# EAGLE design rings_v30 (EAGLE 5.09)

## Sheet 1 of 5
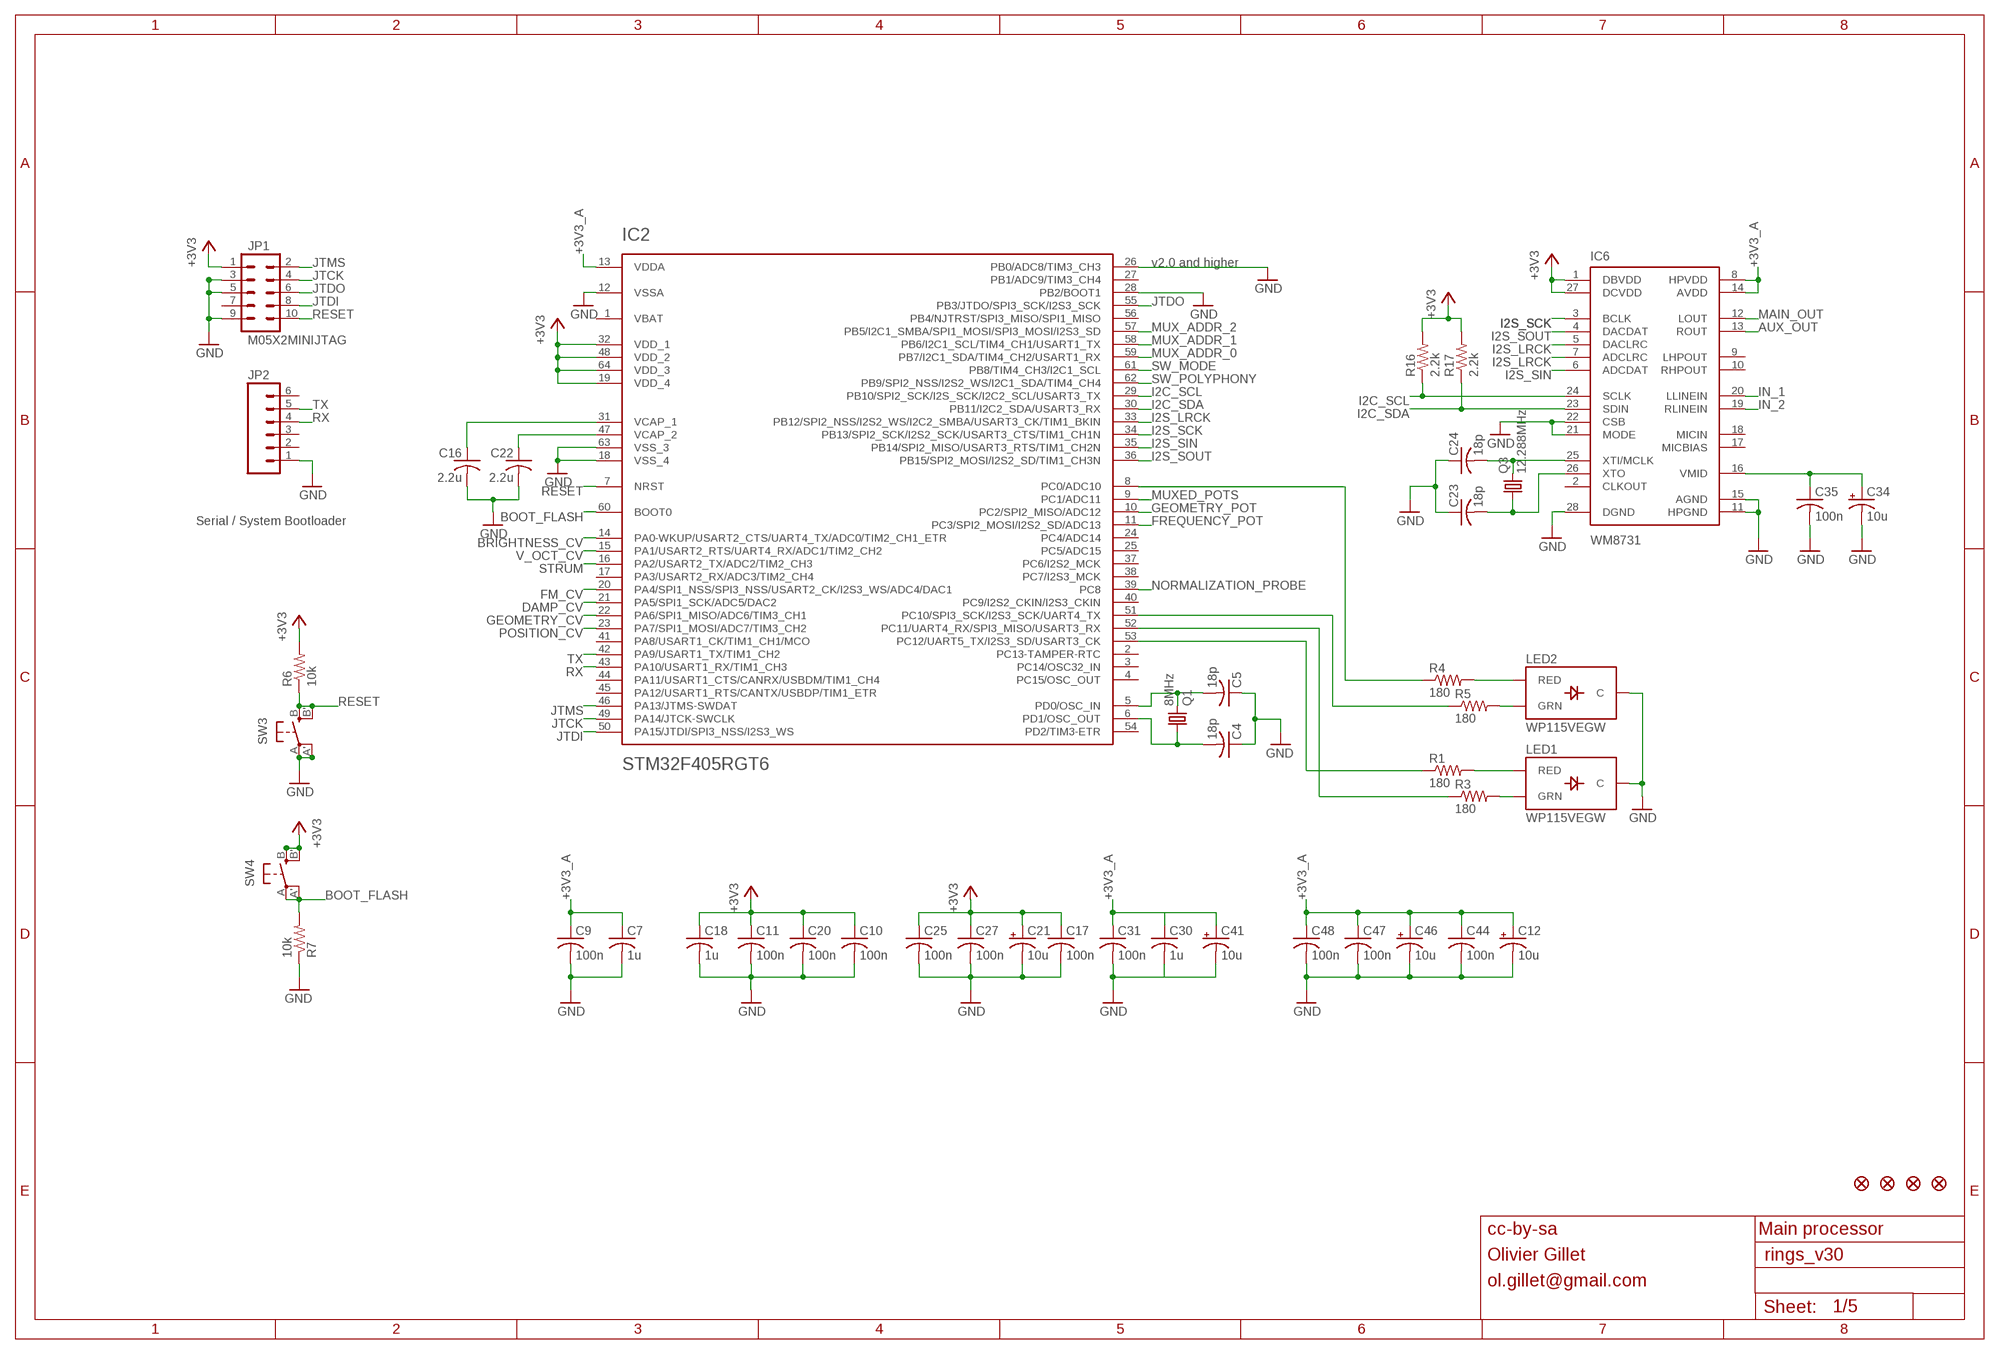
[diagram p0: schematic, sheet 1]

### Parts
C4  18p  C-USC0603  [C0603]
C5  18p  C-USC0603  [C0603]
C7  1u  C-USC0603  [C0603]
C9  100n  C-USC0603  [C0603]
C10  100n  C-USC0603  [C0603]
C11  100n  C-USC0603  [C0603]
C12  10u  CPOL-USA  [PANASONIC_A]
C16  2.2u  C-USC0805  [C0805]
C17  100n  C-USC0603  [C0603]
C18  1u  C-USC0603  [C0603]
C20  100n  C-USC0603  [C0603]
C21  10u  CPOL-USA  [PANASONIC_A]
C22  2.2u  C-USC0805  [C0805]
C23  18p  C-USC0603  [C0603]
C24  18p  C-USC0603  [C0603]
C25  100n  C-USC0603  [C0603]
C27  100n  C-USC0603  [C0603]
C30  1u  C-USC0603  [C0603]
C31  100n  C-USC0603  [C0603]
C34  10u  CPOL-USA  [PANASONIC_A]
C35  100n  C-USC0603  [C0603]
C41  10u  CPOL-USA  [PANASONIC_A]
C44  100n  C-USC0603  [C0603]
C46  10u  CPOL-USA  [PANASONIC_A]
C47  100n  C-USC0603  [C0603]
C48  100n  C-USC0603  [C0603]
F1  FIDUCIAL1X2  [FIDUCIAL-1X2]
F2  FIDUCIAL1X2  [FIDUCIAL-1X2]
F3  FIDUCIAL1X2  [FIDUCIAL-1X2]
F4  FIDUCIAL1X2  [FIDUCIAL-1X2]
IC2  STM32F405RGT6  STM32F20X  [TQFP-10X10-64]
IC6  WM8731  [SSOP28]
JP1  M05X2MINIJTAG  [2X5-1.27]
JP2  M06SIP  [1X06]
LED1  WP115VEGW  LED-BICOLOR-THROUGHHOLE  [LED-BICOLOR-THROUGHHOLE]
LED2  WP115VEGW  LED-BICOLOR-THROUGHHOLE  [LED-BICOLOR-THROUGHHOLE]
Q1  8MHz  CRYSTALHC49UP  [HC49UP]
Q3  12.288MHz  CRYSTALHC49UP  [HC49UP]
R1  180  R-US_R0603  [R0603]
R3  180  R-US_R0603  [R0603]
R4  180  R-US_R0603  [R0603]
R5  180  R-US_R0603  [R0603]
R6  10k  R-US_R0603  [R0603]
R7  10k  R-US_R0603  [R0603]
R16  2.2k  R-US_R0603  [R0603]
R17  2.2k  R-US_R0603  [R0603]
SW3  EVQQ2  [EVQ-Q2]
SW4  EVQQ2  [EVQ-Q2]

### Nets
+3V3: C10.1 C11.1 C17.1 C18.1 C20.1 C21.+ C25.1 C27.1 IC2.19(VDD_4) IC2.32(VDD_1) IC2.48(VDD_2) IC2.64(VDD_3) IC6.1(DBVDD) IC6.27(DCVDD) JP1.1 R6.2 R16.2 R17.2 SW4.B'(S1) SW4.B(S) ; also sheet 4,5
+3V3_A: C7.1 C9.1 C12.+ C30.1 C31.1 C41.+ C44.1 C46.+ C47.1 C48.1 IC2.13(VDDA) IC6.8(HPVDD) IC6.14(AVDD) ; also sheet 2,3,5
AUX_OUT: IC6.13(ROUT) ; also sheet 4
BOOT_FLASH: IC2.60(BOOT0) R7.2 SW4.A'(P1) SW4.A(P)
BRIGHTNESS_CV: IC2.14(PA0-WKUP/USART2_CTS/UART4_TX/ADC0/TIM2_CH1_ETR) ; also sheet 3
DAMP_CV: IC2.21(PA5/SPI1_SCK/ADC5/DAC2) ; also sheet 3
FM_CV: IC2.20(PA4/SPI1_NSS/SPI3_NSS/USART2_CK/I2S3_WS/ADC4/DAC1) ; also sheet 3
FREQUENCY_POT: IC2.11(PC3/SPI2_MOSI/I2S2_SD/ADC13) ; also sheet 2
GEOMETRY_CV: IC2.22(PA6/SPI1_MISO/ADC6/TIM3_CH1) ; also sheet 3
GEOMETRY_POT: IC2.10(PC2/SPI2_MISO/ADC12) ; also sheet 2
GND: C4.1 C5.1 C7.2 C9.2 C10.2 C11.2 C12.- C16.2 C17.2 C18.2 C20.2 C21.- C22.2 C23.1 C24.1 C25.2 C27.2 C30.2 C31.2 C34.- C35.2 C41.- C44.2 C46.- C47.2 C48.2 IC2.12(VSSA) IC2.18(VSS_4) IC2.26(PB0/ADC8/TIM3_CH3) IC2.28(PB2/BOOT1) IC2.63(VSS_3) IC6.11(HPGND) IC6.15(AGND) IC6.21(MODE) IC6.22(CSB) IC6.28(DGND) JP1.3 JP1.5 JP1.9 JP2.1 LED1.2(C) LED2.2(C) R7.1 SW3.A'(P1) SW3.A(P) ; also sheet 2,3,4,5
I2C_SCL: IC2.29(PB10/SPI2_SCK/I2S_SCK/I2C2_SCL/USART3_TX) IC6.24(SCLK) R16.1
I2C_SDA: IC2.30(PB11/I2C2_SDA/USART3_RX) IC6.23(SDIN) R17.1
I2S_LRCK: IC2.33(PB12/SPI2_NSS/I2S2_WS/I2C2_SMBA/USART3_CK/TIM1_BKIN) IC6.5(DACLRC) IC6.7(ADCLRC)
I2S_SCK: IC2.34(PB13/SPI2_SCK/I2S2_SCK/USART3_CTS/TIM1_CH1N) IC6.3(BCLK)
I2S_SIN: IC2.35(PB14/SPI2_MISO/USART3_RTS/TIM1_CH2N) IC6.6(ADCDAT)
I2S_SOUT: IC2.36(PB15/SPI2_MOSI/I2S2_SD/TIM1_CH3N) IC6.4(DACDAT)
IN_1: IC6.20(LLINEIN) ; also sheet 4
IN_2: IC6.19(RLINEIN) ; also sheet 4
JTCK: IC2.49(PA14/JTCK-SWCLK) JP1.4
JTDI: IC2.50(PA15/JTDI/SPI3_NSS/I2S3_WS) JP1.8
JTDO: IC2.55(PB3/JTDO/SPI3_SCK/I2S3_SCK) JP1.6
JTMS: IC2.46(PA13/JTMS-SWDAT) JP1.2
MAIN_OUT: IC6.12(LOUT) ; also sheet 4
MUX_ADDR_0: IC2.59(PB7/I2C1_SDA/TIM4_CH2/USART1_RX) ; also sheet 2
MUX_ADDR_1: IC2.58(PB6/I2C1_SCL/TIM4_CH1/USART1_TX) ; also sheet 2
MUX_ADDR_2: IC2.57(PB5/I2C1_SMBA/SPI1_MOSI/SPI3_MOSI/I2S3_SD) ; also sheet 2
MUXED_POTS: IC2.9(PC1/ADC11) ; also sheet 2
N$7: C5.2 IC2.5(PD0/OSC_IN) Q1.2
N$8: C4.2 IC2.6(PD1/OSC_OUT) Q1.1
N$12: LED1.3(RED) R1.2
N$13: C22.1 IC2.47(VCAP_2)
N$17: C34.+ C35.1 IC6.16(VMID)
N$19: C16.1 IC2.31(VCAP_1)
N$22: LED1.1(GRN) R3.2
N$27: LED2.3(RED) R4.2
N$35: LED2.1(GRN) R5.2
N$37: IC2.52(PC11/UART4_RX/SPI3_MISO/USART3_RX) R3.1
N$40: IC2.8(PC0/ADC10) R4.1
N$41: C24.2 IC6.25(XTI/MCLK) Q3.2
N$42: C23.2 IC6.26(XTO) Q3.1
N$43: IC2.53(PC12/UART5_TX/I2S3_SD/USART3_CK) R1.1
N$44: IC2.51(PC10/SPI3_SCK/I2S3_SCK/UART4_TX) R5.1
NORMALIZATION_PROBE: IC2.39(PC8) ; also sheet 4
POSITION_CV: IC2.23(PA7/SPI1_MOSI/ADC7/TIM3_CH2) ; also sheet 3
RESET: IC2.7(NRST) JP1.10 R6.1 SW3.B'(S1) SW3.B(S)
RX: IC2.43(PA10/USART1_RX/TIM1_CH3) JP2.4
STRUM: IC2.16(PA2/USART2_TX/ADC2/TIM2_CH3) ; also sheet 4
SW_MODE: IC2.61(PB8/TIM4_CH3/I2C1_SCL) ; also sheet 2
SW_POLYPHONY: IC2.62(PB9/SPI2_NSS/I2S2_WS/I2C1_SDA/TIM4_CH4) ; also sheet 2
TX: IC2.42(PA9/USART1_TX/TIM1_CH2) JP2.5
V_OCT_CV: IC2.15(PA1/USART2_RTS/UART4_RX/ADC1/TIM2_CH2) ; also sheet 3
Unconnected: IC2.2(PC13-TAMPER-RTC) IC2.3(PC14/OSC32_IN) IC2.4(PC15/OSC_OUT) IC2.17(PA3/USART2_RX/ADC3/TIM2_CH4) IC2.24(PC4/ADC14) IC2.25(PC5/ADC15) IC2.27(PB1/ADC9/TIM3_CH4) IC2.37(PC6/I2S2_MCK) IC2.38(PC7/I2S3_MCK) IC2.40(PC9/I2S2_CKIN/I2S3_CKIN) IC2.41(PA8/USART1_CK/TIM1_CH1/MCO) IC2.44(PA11/USART1_CTS/CANRX/USBDM/TIM1_CH4) IC2.45(PA12/USART1_RTS/CANTX/USBDP/TIM1_ETR) IC2.54(PD2/TIM3-ETR) IC2.56(PB4/NJTRST/SPI3_MISO/SPI1_MISO) IC6.2(CLKOUT) IC6.9(LHPOUT) IC6.10(RHPOUT) IC6.17(MICBIAS) IC6.18(MICIN) JP1.7 JP2.2 JP2.3 JP2.6

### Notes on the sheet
- v2.0 and higher
- Serial / System Bootloader
- cc-by-sa | Main processor
- Olivier Gillet
- ol.gillet@gmail.com

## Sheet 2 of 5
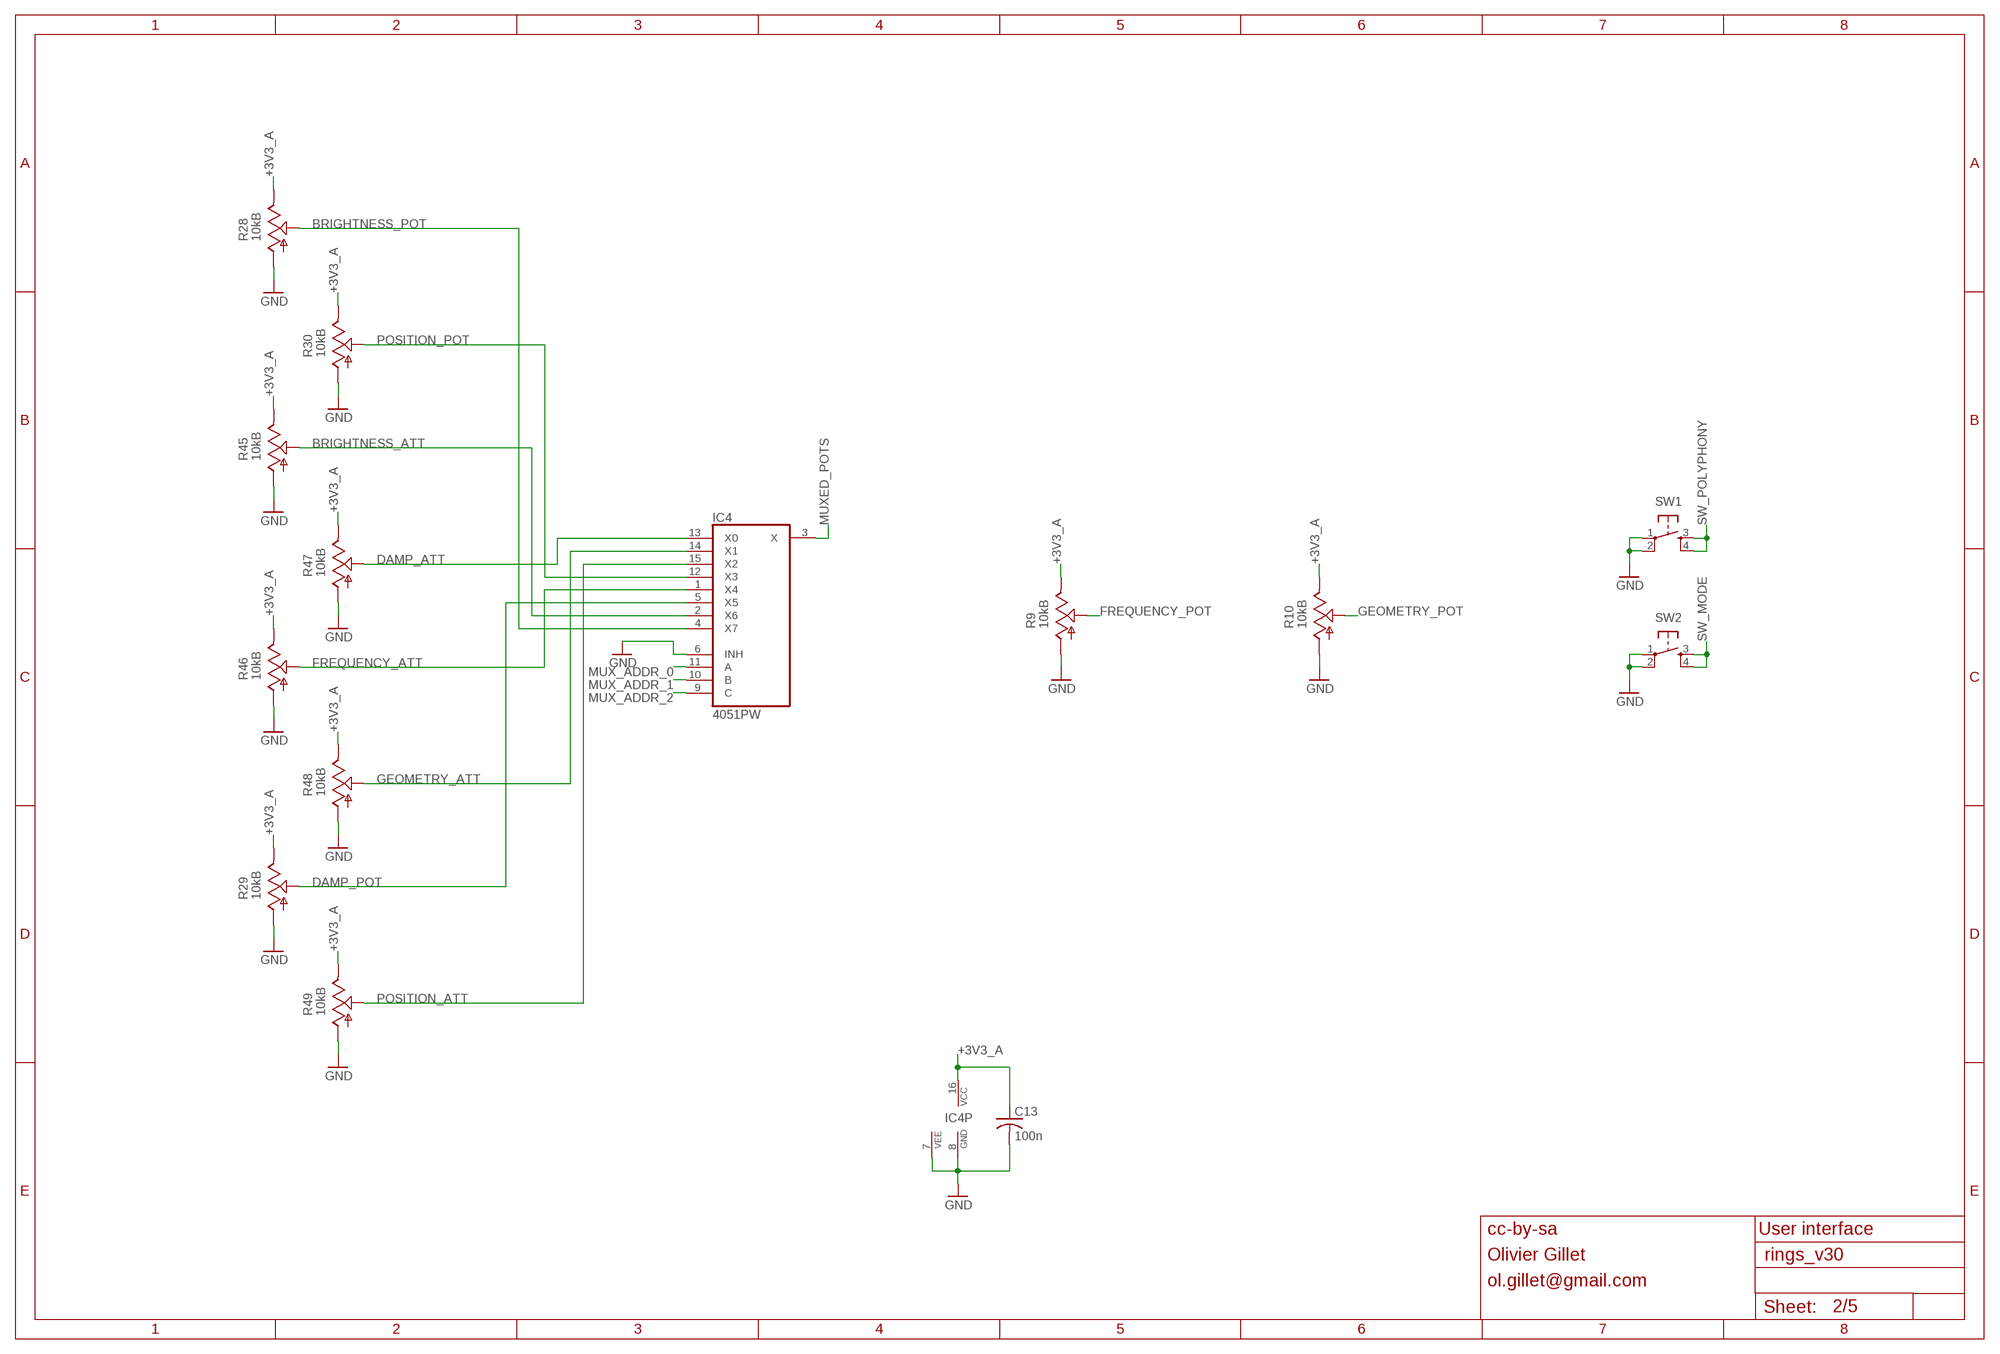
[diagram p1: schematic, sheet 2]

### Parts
C13  100n  C-USC0603  [C0603]
IC4  4051PW  [TSSOP16]
R9  10kB  POT_USVERTICAL_PS  [ALPS_POT_VERTICAL_PS]
R10  10kB  POT_USVERTICAL_PS  [ALPS_POT_VERTICAL_PS]
R28  10kB  POT_USVERTICAL_PS  [ALPS_POT_VERTICAL_PS]
R29  10kB  POT_USVERTICAL_PS  [ALPS_POT_VERTICAL_PS]
R30  10kB  POT_USVERTICAL_PS  [ALPS_POT_VERTICAL_PS]
R45  10kB  POT_USVERTICAL  [ALPS_POT_VERTICAL]
R46  10kB  POT_USVERTICAL  [ALPS_POT_VERTICAL]
R47  10kB  POT_USVERTICAL  [ALPS_POT_VERTICAL]
R48  10kB  POT_USVERTICAL  [ALPS_POT_VERTICAL]
R49  10kB  POT_USVERTICAL  [ALPS_POT_VERTICAL]
SW1  TAC_SWITCHPTH  [TACTILE-PTH]
SW2  TAC_SWITCHPTH  [TACTILE-PTH]

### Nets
+3V3_A: C13.1 IC4.16(VCC) R9.P$1(E) R10.P$1(E) R28.P$1(E) R29.P$1(E) R30.P$1(E) R45.P$1(E) R46.P$1(E) R47.P$1(E) R48.P$1(E) R49.P$1(E) ; also sheet 1,3,5
BRIGHTNESS_ATT: IC4.2(X6) R45.P$2(S)
BRIGHTNESS_POT: IC4.4(X7) R28.P$2(S)
DAMP_ATT: IC4.13(X0) R47.P$2(S)
DAMP_POT: IC4.5(X5) R29.P$2(S)
FREQUENCY_ATT: IC4.1(X4) R46.P$2(S)
FREQUENCY_POT: R9.P$2(S) ; also sheet 1
GEOMETRY_ATT: IC4.14(X1) R48.P$2(S)
GEOMETRY_POT: R10.P$2(S) ; also sheet 1
GND: C13.2 IC4.6(INH) IC4.7(VEE) IC4.8(GND) R9.P$3(A) R10.P$3(A) R28.P$3(A) R29.P$3(A) R30.P$3(A) R45.P$3(A) R46.P$3(A) R47.P$3(A) R48.P$3(A) R49.P$3(A) SW1.1 SW1.2 SW2.1 SW2.2 ; also sheet 1,3,4,5
MUX_ADDR_0: IC4.11(A) ; also sheet 1
MUX_ADDR_1: IC4.10(B) ; also sheet 1
MUX_ADDR_2: IC4.9(C) ; also sheet 1
MUXED_POTS: IC4.3(X) ; also sheet 1
POSITION_ATT: IC4.15(X2) R49.P$2(S)
POSITION_POT: IC4.12(X3) R30.P$2(S)
SW_MODE: SW2.3 SW2.4 ; also sheet 1
SW_POLYPHONY: SW1.3 SW1.4 ; also sheet 1

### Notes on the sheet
- cc-by-sa | User interface
- Olivier Gillet
- ol.gillet@gmail.com

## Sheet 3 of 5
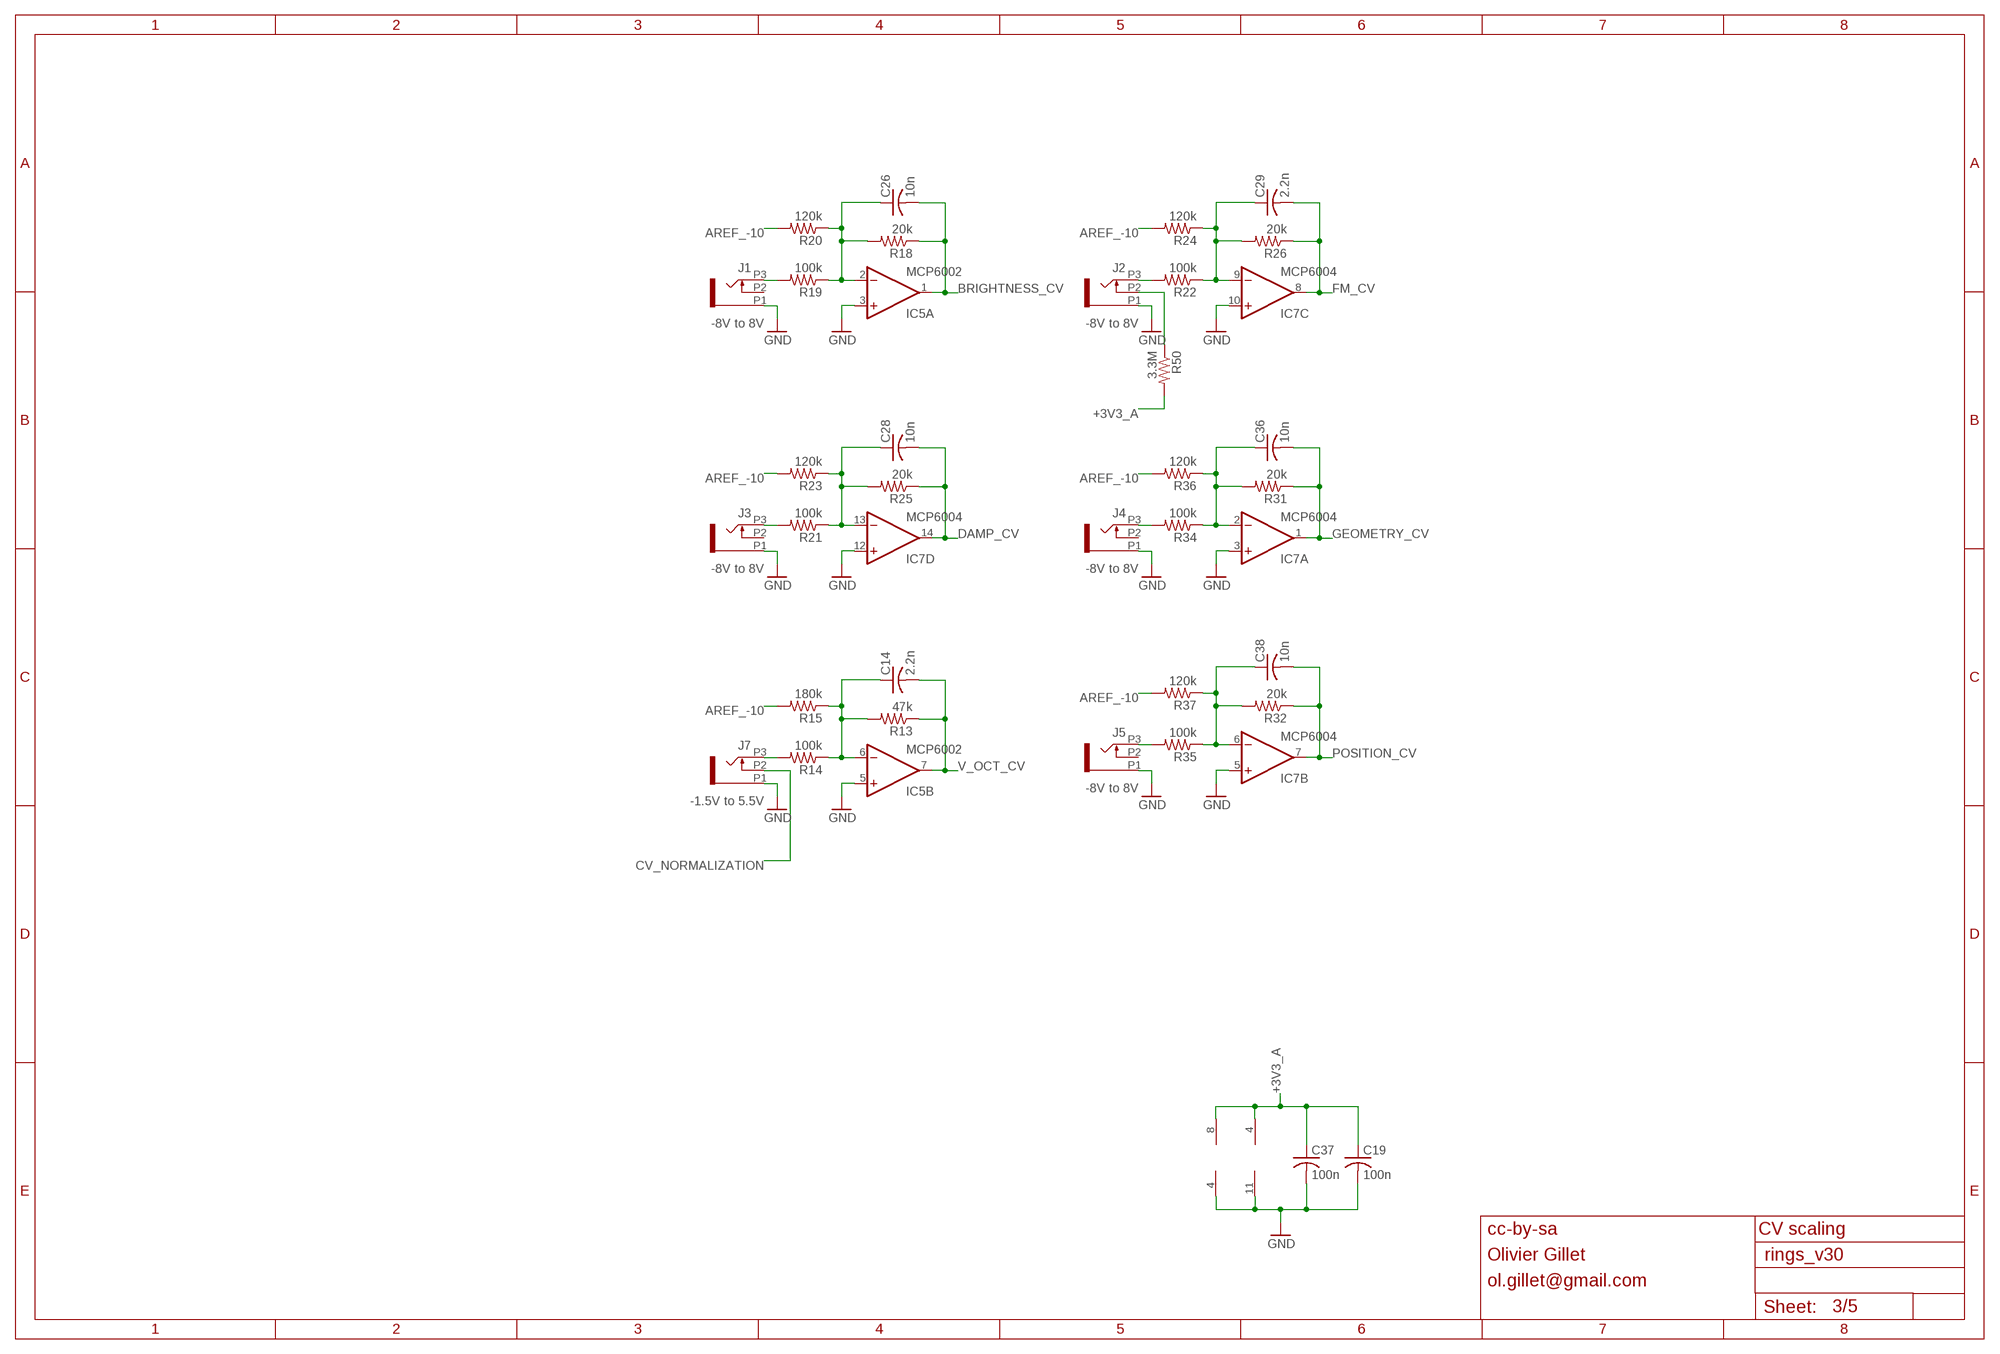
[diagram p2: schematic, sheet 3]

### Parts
C14  2.2n  C-USC0603  [C0603]
C19  100n  C-USC0603  [C0603]
C26  10n  C-USC0603  [C0603]
C28  10n  C-USC0603  [C0603]
C29  2.2n  C-USC0603  [C0603]
C36  10n  C-USC0603  [C0603]
C37  100n  C-USC0603  [C0603]
C38  10n  C-USC0603  [C0603]
IC5  MCP6002  TL072D  [SO08]
IC7  MCP6004  TL074D  [SO14]
J1  PJ301_THONKICONN6  [WQP_PJ_301M6]
J2  PJ301_THONKICONN6  [WQP_PJ_301M6]
J3  PJ301_THONKICONN6  [WQP_PJ_301M6]
J4  PJ301_THONKICONN6  [WQP_PJ_301M6]
J5  PJ301_THONKICONN6  [WQP_PJ_301M6]
J7  PJ301_THONKICONN6  [WQP_PJ_301M6]
R13  47k  R-US_R0603  [R0603]
R14  100k  R-US_R0603  [R0603]
R15  180k  R-US_R0603  [R0603]
R18  20k  R-US_R0603  [R0603]
R19  100k  R-US_R0603  [R0603]
R20  120k  R-US_R0603  [R0603]
R21  100k  R-US_R0603  [R0603]
R22  100k  R-US_R0603  [R0603]
R23  120k  R-US_R0603  [R0603]
R24  120k  R-US_R0603  [R0603]
R25  20k  R-US_R0603  [R0603]
R26  20k  R-US_R0603  [R0603]
R31  20k  R-US_R0603  [R0603]
R32  20k  R-US_R0603  [R0603]
R34  100k  R-US_R0603  [R0603]
R35  100k  R-US_R0603  [R0603]
R36  120k  R-US_R0603  [R0603]
R37  120k  R-US_R0603  [R0603]
R50  3.3M  R-US_R0603  [R0603]

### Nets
+3V3_A: C19.1 C37.1 IC5.8(P:V+) IC7.4(P:V+) R50.2 ; also sheet 1,2,5
AREF_-10: R15.2 R20.2 R23.2 R24.2 R36.2 R37.2 ; also sheet 5
BRIGHTNESS_CV: C26.2 IC5.1(A:OUT) R18.1 ; also sheet 1
CV_NORMALIZATION: J7.P2 ; also sheet 4
DAMP_CV: C28.2 IC7.14(D:OUT) R25.1 ; also sheet 1
FM_CV: C29.2 IC7.8(C:OUT) R26.1 ; also sheet 1
GEOMETRY_CV: C36.2 IC7.1(A:OUT) R31.1 ; also sheet 1
GND: C19.2 C37.2 IC5.3(A:+IN) IC5.4(P:V-) IC5.5(B:+IN) IC7.3(A:+IN) IC7.5(B:+IN) IC7.10(C:+IN) IC7.11(P:V-) IC7.12(D:+IN) J1.P1 J2.P1 J3.P1 J4.P1 J5.P1 J7.P1 ; also sheet 1,2,4,5
N$1: J1.P3 R19.2
N$2: C26.1 IC5.2(A:-IN) R18.2 R19.1 R20.1
N$3: J7.P3 R14.2
N$4: J2.P3 R22.2
N$5: C29.1 IC7.9(C:-IN) R22.1 R24.1 R26.2
N$6: J4.P3 R34.2
N$10: J3.P3 R21.2
N$11: C28.1 IC7.13(D:-IN) R21.1 R23.1 R25.2
N$14: C14.1 IC5.6(B:-IN) R13.2 R14.1 R15.1
N$15: C36.1 IC7.2(A:-IN) R31.2 R34.1 R36.1
N$26: J5.P3 R35.2
N$30: C38.1 IC7.6(B:-IN) R32.2 R35.1 R37.1
N$38: J2.P2 R50.1
POSITION_CV: C38.2 IC7.7(B:OUT) R32.1 ; also sheet 1
V_OCT_CV: C14.2 IC5.7(B:OUT) R13.1 ; also sheet 1
Unconnected: J1.P2 J3.P2 J4.P2 J5.P2

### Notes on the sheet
- -8V to 8V | -8V to 8V
- -8V to 8V | -8V to 8V
- -8V to 8V
- -1.5V to 5.5V
- cc-by-sa | CV scaling
- Olivier Gillet
- ol.gillet@gmail.com

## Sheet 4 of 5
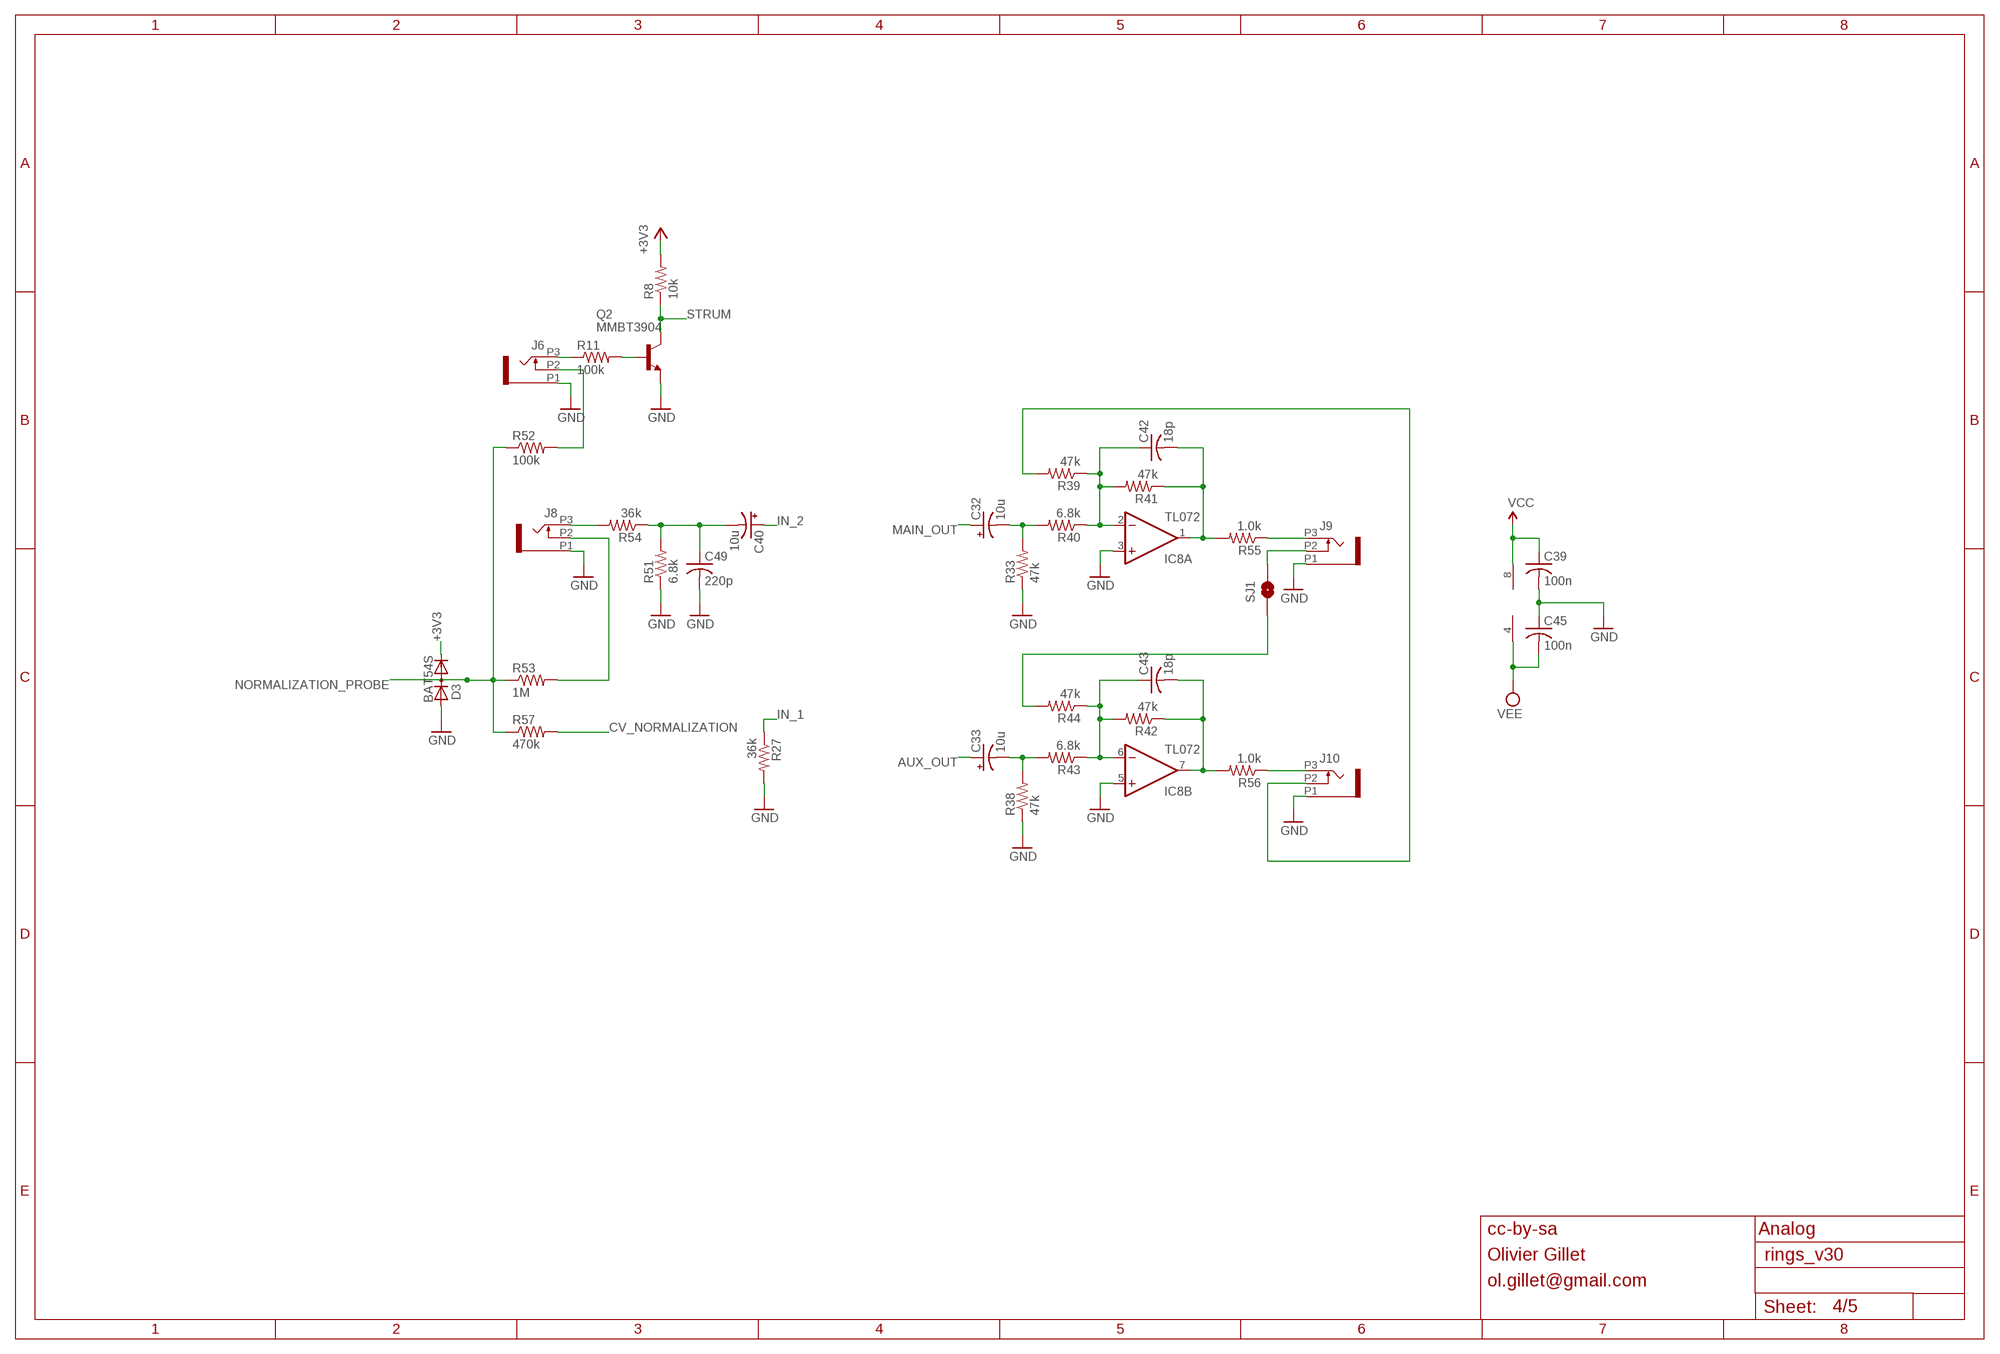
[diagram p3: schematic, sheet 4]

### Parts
C32  10u  CPOL-USA  [PANASONIC_A]
C33  10u  CPOL-USA  [PANASONIC_A]
C39  100n  C-USC0603  [C0603]
C40  10u  CPOL-USA  [PANASONIC_A]
C42  18p  C-USC0603  [C0603]
C43  18p  C-USC0603  [C0603]
C45  100n  C-USC0603  [C0603]
C49  220p  C-USC0603  [C0603]
D3  BAT54S  DIODE_2CACA-SOT23  [SOT23]
IC8  TL072  TL072D  [SO08]
J6  PJ301_THONKICONN6  [WQP_PJ_301M6]
J8  PJ301_THONKICONN6  [WQP_PJ_301M6]
J9  PJ301_THONKICONN6  [WQP_PJ_301M6]
J10  PJ301_THONKICONN6  [WQP_PJ_301M6]
Q2  MMBT3904  MMBT3904LT1-NPN-SOT23-BEC  [SOT23-BEC]
R8  10k  R-US_R0603  [R0603]
R11  100k  R-US_R0603  [R0603]
R27  36k  R-US_R0603  [R0603]
R33  47k  R-US_R0603  [R0603]
R38  47k  R-US_R0603  [R0603]
R39  47k  R-US_R0603  [R0603]
R40  6.8k  R-US_R0603  [R0603]
R41  47k  R-US_R0603  [R0603]
R42  47k  R-US_R0603  [R0603]
R43  6.8k  R-US_R0603  [R0603]
R44  47k  R-US_R0603  [R0603]
R51  6.8k  R-US_R0603  [R0603]
R52  100k  R-US_R0603  [R0603]
R53  1M  R-US_R0603  [R0603]
R54  36k  R-US_R0603  [R0603]
R55  1.0k  R-US_R0603  [R0603]
R56  1.0k  R-US_R0603  [R0603]
R57  470k  R-US_R0603  [R0603]
SJ1  SOLDERJUMPERNC2  [SJ_2S-NOTRACE]

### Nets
+3V3: D3.2(C) R8.2 ; also sheet 1,5
AUX_OUT: C33.+ ; also sheet 1
CV_NORMALIZATION: R57.2 ; also sheet 3
GND: C39.2 C45.1 C49.2 D3.1(A) IC8.3(A:+IN) IC8.5(B:+IN) J6.P1 J8.P1 J9.P1 J10.P1 Q2.E R27.2 R33.1 R38.1 R51.1 ; also sheet 1,2,3,5
IN_1: R27.1 ; also sheet 1
IN_2: C40.+ ; also sheet 1
MAIN_OUT: C32.+ ; also sheet 1
N$9: J6.P3 R11.1
N$18: C40.- C49.1 R51.2 R54.1
N$20: J6.P2 R52.2
N$21: J8.P3 R54.2
N$23: C33.- R38.2 R43.2
N$25: C43.1 IC8.6(B:-IN) R42.2 R43.1 R44.1
N$28: C43.2 IC8.7(B:OUT) R42.1 R56.2
N$29: J10.P3 R56.1
N$31: C32.- R33.2 R40.2
N$32: C42.1 IC8.2(A:-IN) R39.1 R40.1 R41.2
N$33: C42.2 IC8.1(A:OUT) R41.1 R55.2
N$34: J9.P3 R55.1
N$39: J8.P2 R53.2
N$45: J10.P2 R39.2
N$46: R44.2 SJ1.1
N$47: J9.P2 SJ1.2
N$66: Q2.B R11.2
NORMALIZATION_PROBE: D3.3(AC) R52.1 R53.1 R57.1 ; also sheet 1
STRUM: Q2.C R8.1 ; also sheet 1
VCC: C39.1 IC8.8(P:V+) ; also sheet 5
VEE: C45.2 IC8.4(P:V-) ; also sheet 5

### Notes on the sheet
- cc-by-sa | Analog
- Olivier Gillet
- ol.gillet@gmail.com

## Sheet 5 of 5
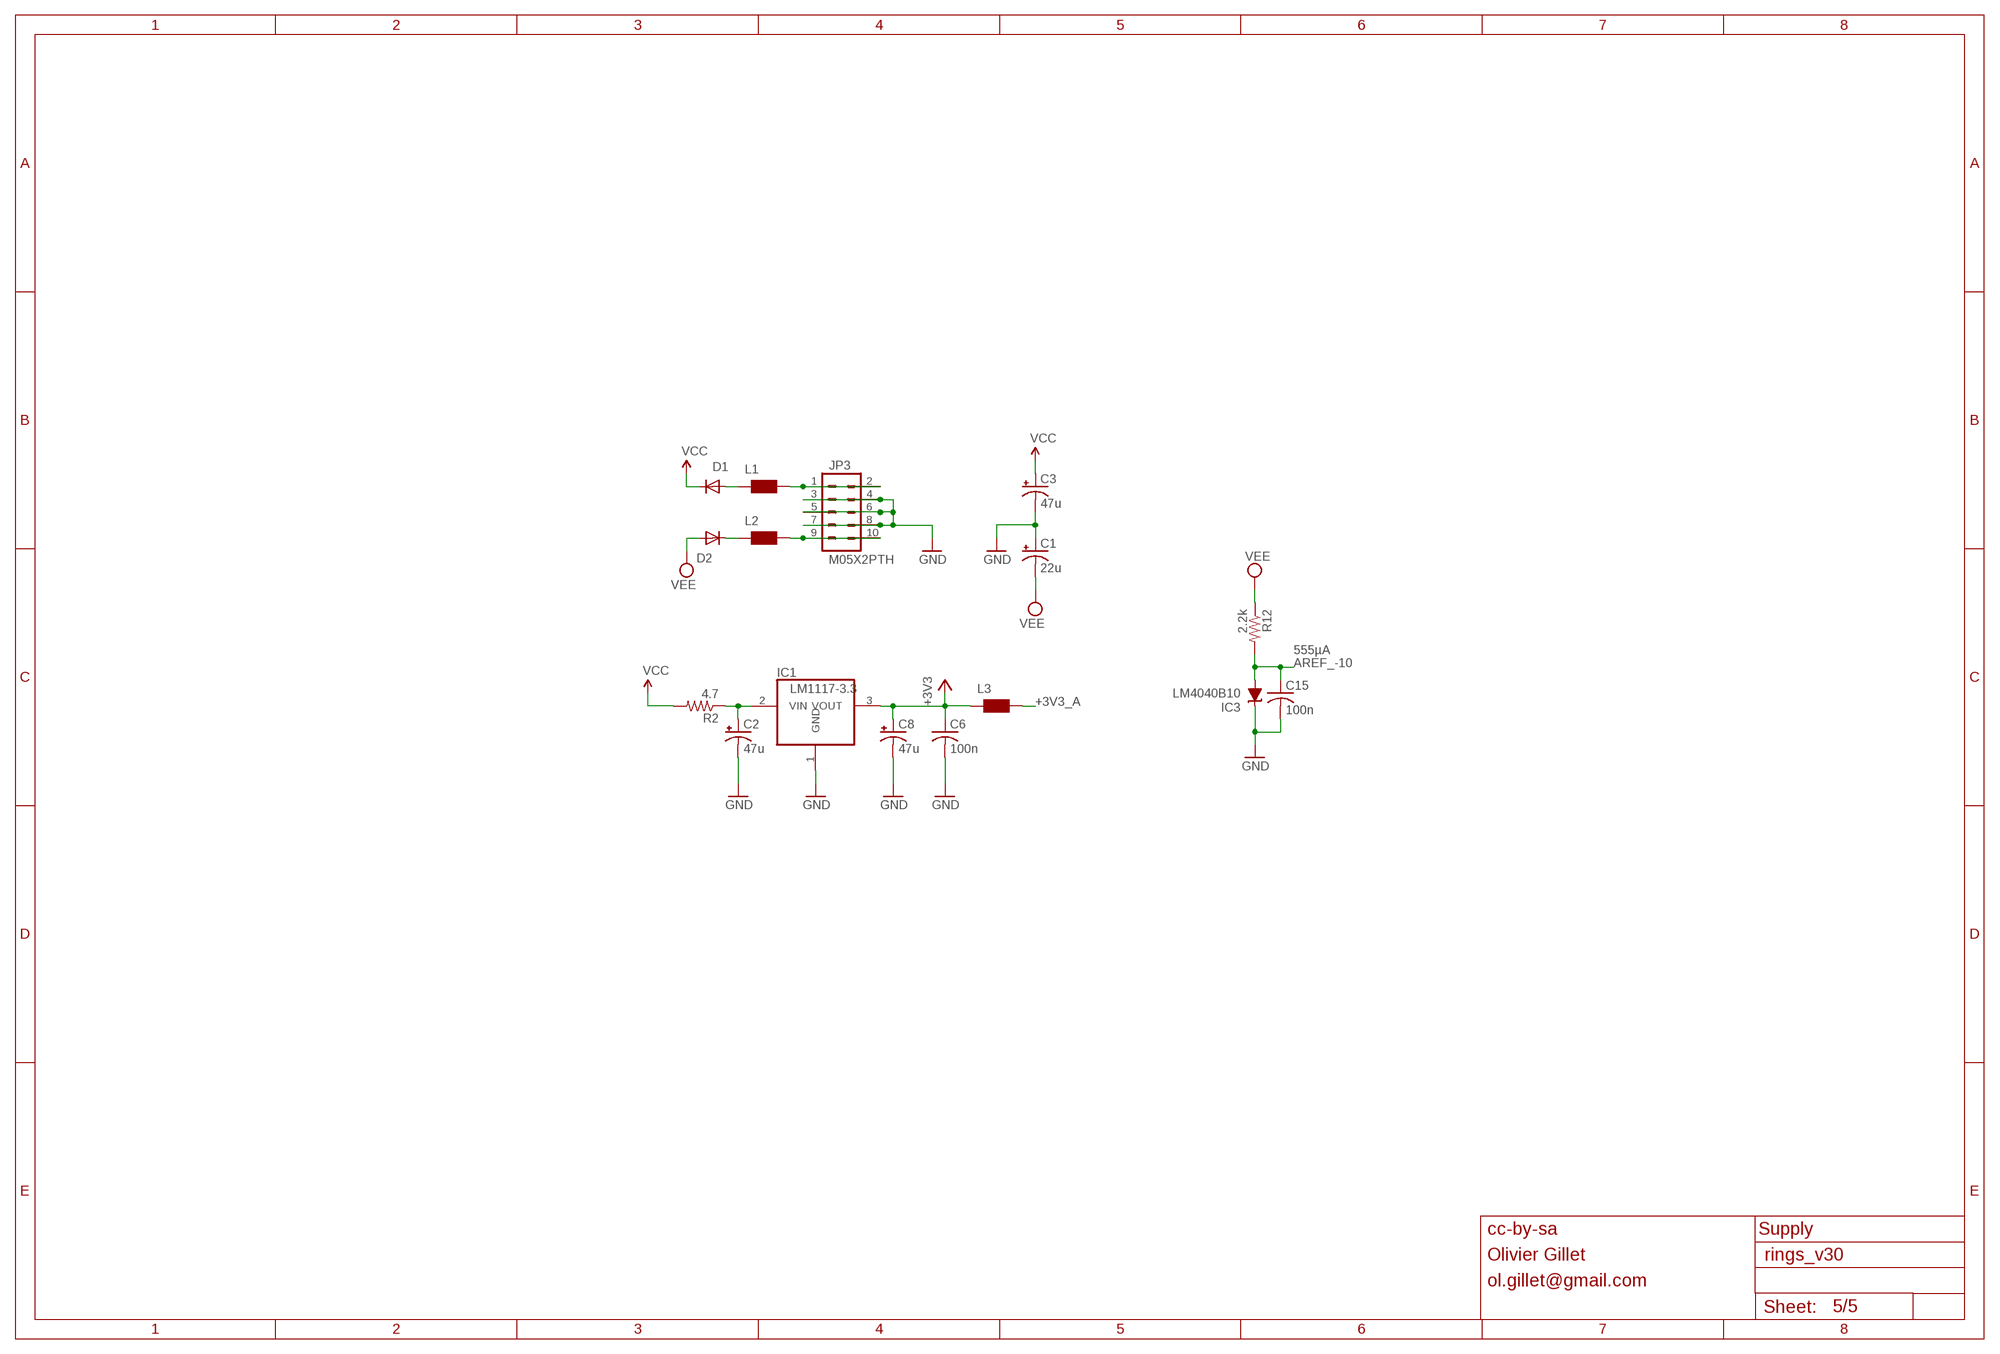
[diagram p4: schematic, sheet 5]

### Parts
C1  22u  CPOL-USC  [PANASONIC_C]
C2  47u  CPOL-USD  [PANASONIC_D]
C3  47u  CPOL-USD  [PANASONIC_D]
C6  100n  C-USC0603  [C0603]
C8  47u  CPOL-USD  [PANASONIC_D]
C15  100n  C-USC0603  [C0603]
D1  1N5819HW  DIODE-SOD123  [SOD123]
D2  1N5819HW  DIODE-SOD123  [SOD123]
IC1  LM1117-3.3  REG1117T  [TO252]
IC3  LM4040B10  LM4041B12DBZ  [DBZ_R-PDSO-G3]
JP3  M05X2PTH  [AVR_ICSP]
L1  WE-CBF_0603  [0603]
L2  WE-CBF_0603  [0603]
L3  WE-CBF_0603  [0603]
R2  4.7  R-US_R1206  [R1206]
R12  2.2k  R-US_R0603  [R0603]

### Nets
+3V3: C6.1 C8.+ IC1.3(VOUT) L3.1 ; also sheet 1,4
+3V3_A: L3.2 ; also sheet 1,2,3
AREF_-10: C15.1 IC3.2(A) R12.2 ; also sheet 3
GND: C1.+ C2.- C3.- C6.2 C8.- C15.2 IC1.1(GND) IC3.1(C) JP3.3 JP3.4 JP3.5 JP3.6 JP3.7 JP3.8 ; also sheet 1,2,3,4
N$16: C2.+ IC1.2(VIN) R2.1
N$24: D1.A L1.1
N$36: D2.C L2.1
N$56: JP3.1 JP3.2 L1.2
N$64: JP3.9 JP3.10 L2.2
VCC: C3.+ D1.C R2.2 ; also sheet 4
VEE: C1.- D2.A R12.1 ; also sheet 4

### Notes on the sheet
- 555µA
- cc-by-sa | Supply
- Olivier Gillet
- ol.gillet@gmail.com

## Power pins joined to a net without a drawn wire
VBAT: IC2.1(VBAT)

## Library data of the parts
C1-C3 C8 C12 C21 C32-C34 C40 C41 C46 = rcl:CPOL-US: POLARIZED CAPACITOR, American symbol
C4-C7 C9-C11 C13-C20 C22-C31 C35-C39 C42-C45 C47-C49 = rcl:C-US: CAPACITOR, American symbol
D1 D2 = diode:DIODE-: DIODE
D3 = diode:DIODE_2CACA-: 2 Diodes - Cathode-Anode|Cathode-Anode
F1-F4 = SparkFun:FIDUCIAL: Fiducial Alignment Points
IC1 = og-vreg:REG1117: 800mA and 1A Low Dropout (LDO) Positive Regulator 1.8V, 2.5V, 2.85V, 3.3V, 5V, and Adj
IC2 = og-stm32f2:STM32F20X
IC3 = texas:LM4041: PRECISION MICROPOWER SHUNT VOLTAGE REFERENCE
IC4 = og-ics:4051: 8-channel ANALOG MULTIPLEXER
IC5 = gm-ics:TL072: OP AMP
IC6 = og-dac:WM8731
IC7 = gm-ics:TL074: OP AMP
IC8 = og-linear:TL072: OP AMP
J1-J10 = og-pj301:PJ301_THONKICONN
JP1 JP3 = og-header:M05X2: Header 5x2 Standard 10-pin dual row 0.1" header. Commonly used with AVR-ISP. Use with Spark Fun Electronics SKU: PRT-00778
JP2 = SparkFun:M06: Header 6 Standard 6-pin 0.1" header. Use with straight break away headers (SKU : PRT-00116), right angle break away headers (PRT-00553), swiss pins (PRT-00743), machine pins (PRT-00117), and female headers (PRT-00115). Molex polarized connector foot print use with SKU : PRT-08094 with associated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
L1-L3 = wuerth-elektronik:WE-CBF: SMD EMI Suppression Ferrite Beads
LED1 LED2 = og-leds:LED-BICOLOR-THROUGHHOLE
Q1 Q3 = crystal:CRYSTAL: CRYSTAL
Q2 = transistor:*-NPN-: NPN Transistror BF959 corrected 2008.03.06
R1-R8 R11-R27 R31-R44 R50-R57 = rcl:R-US_: RESISTOR, American symbol
R9 R10 R28-R30 R45-R49 = og-pots:POT_US
SJ1 = SparkFun:SOLDERJUMPER: Solder Jumper
SW1 SW2 = SparkFun:TAC_SWITCH: Momentary Switch Button commonly used for reset or general input. Spark Fun Electronics SKU : COM-00097
SW3 SW4 = adafruit:EVQQ2: SMT 6mm switch, EVQQ2 series http://www.ladyada.net/library/eagle

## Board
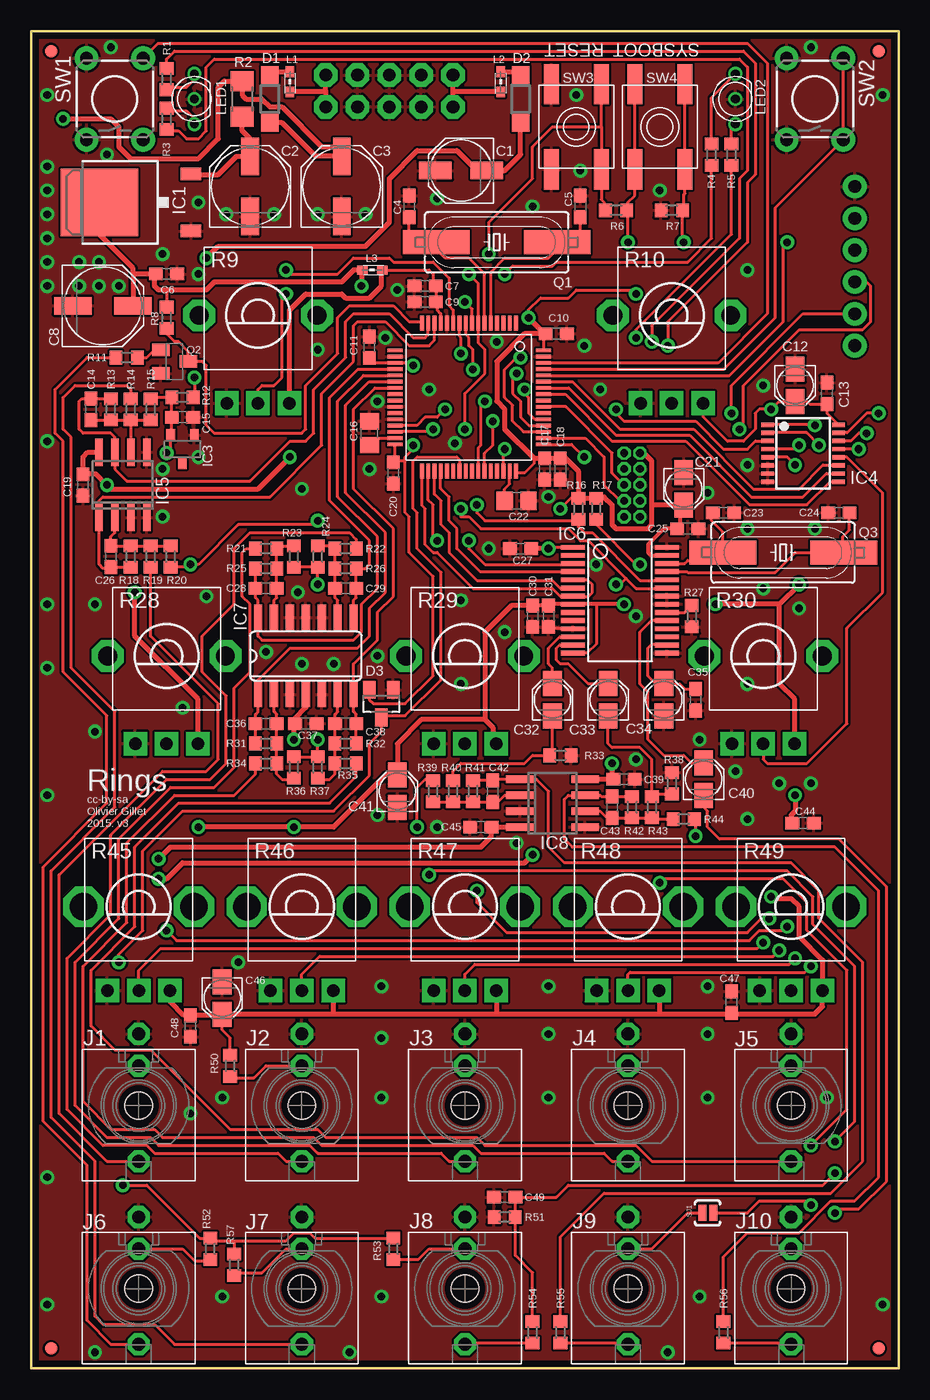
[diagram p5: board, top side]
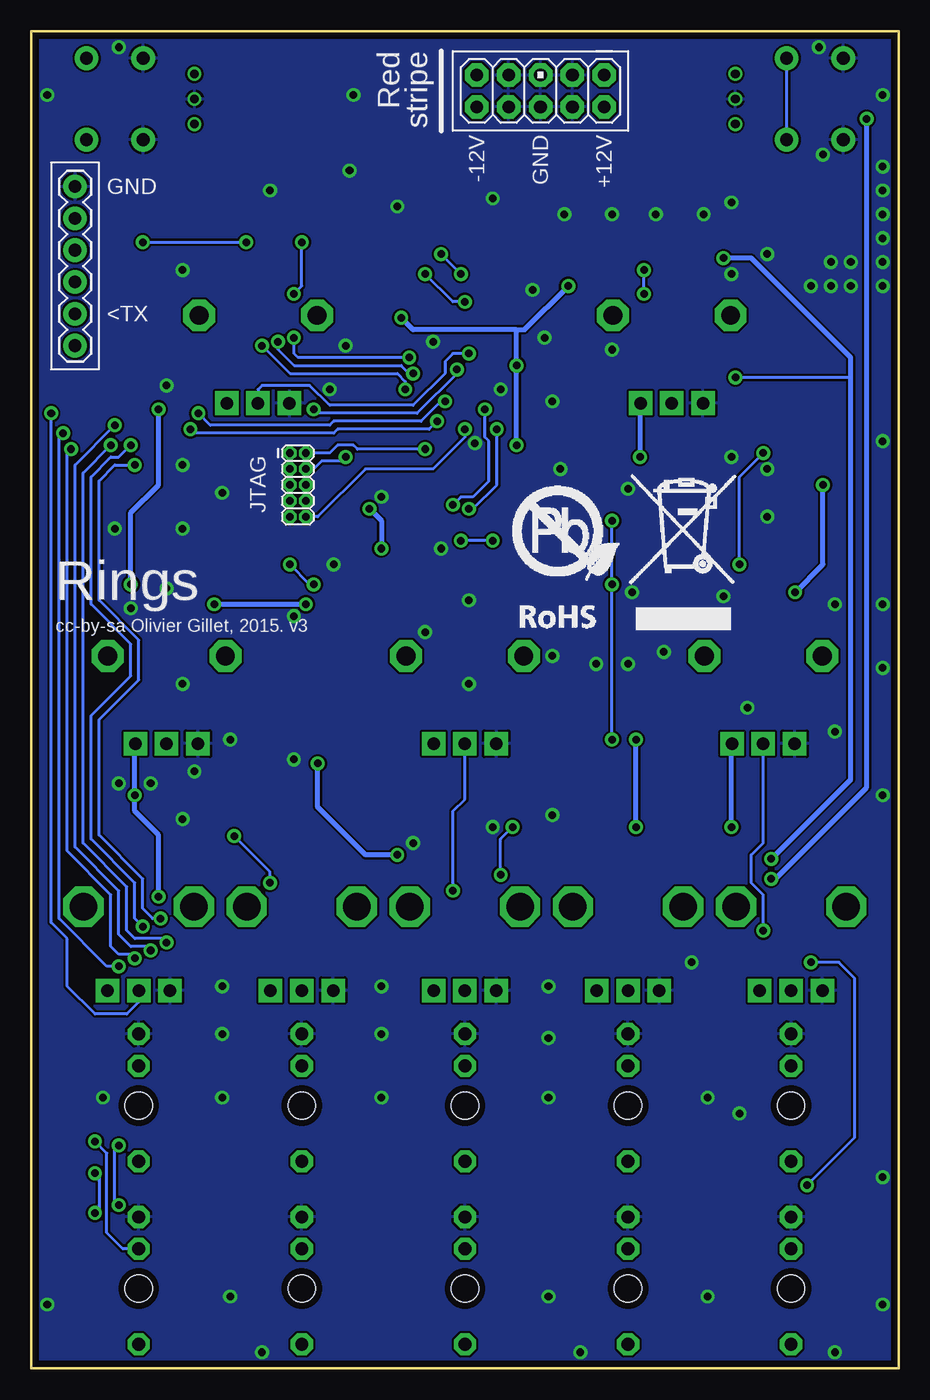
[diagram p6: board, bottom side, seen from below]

Size 69.22 x 106.68 mm. Coordinates in mm from the lower left corner, seen from the top.
Outline: 0,0 69.22,0 69.22,106.68 0,106.68 0,0
Copper layers (1*16): Top 0.035mm / dielectric 1.5mm / Bottom 0.035mm
Design rules "PCBCart-Standard-Fine": minimum track width 8mil, minimum drill 0.4mm, track to track 7mil, track to pad 7mil, pad to pad 7mil, via to via 7mil, smd to smd 7mil, copper to edge 20mil, drill to drill 8mil, minimum pad ring 8mil, minimum via ring 10mil, stop-mask expansion 3mil, vias tented up to drill 25mil, thermal gap 8mil

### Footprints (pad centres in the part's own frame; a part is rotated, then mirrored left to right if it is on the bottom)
PANASONIC_C = smd 2.6 x 1.4: + 2.05,0; - -2.05,0
PANASONIC_D = smd 3 x 1.4: + 2.4,0; - -2.4,0
C0603 = smd 1.1 x 1: 1 -0.85,0; 2 0.85,0
PANASONIC_A = smd 2 x 1.5: + 1.3,0; - -1.3,0
C0805 = smd 1.3 x 1.5: 1 -0.95,0; 2 0.95,0
SOD123 = smd 1.4 x 1.4: A 1.9,0; C -1.9,0
SOT23 = smd 1 x 1.4: 1 -0.95,-1.1; 2 0.95,-1.1; 3 0,1.1
FIDUCIAL-1X2 = smd 1 x 1: 1 0,0
TO252 = smd 1 x 1.6: 1 -2.28,-4.8; 2 2.28,-4.8 | smd 5.4 x 6.2: 3 0,2.5
TQFP-10X10-64 = smd 1.2 x 0.3: 1 -5.936,3.75; 2 -5.936,3.25; 3 -5.936,2.75; 4 -5.936,2.25; 5 -5.936,1.75; 6 -5.936,1.25; 7 -5.936,0.75; 8 -5.936,0.25; 9 -5.936,-0.25; 10 -5.936,-0.75; 11 -5.936,-1.25; 12 -5.936,-1.75; 13 -5.936,-2.25; 14 -5.936,-2.75; 15 -5.936,-3.25; 16 -5.936,-3.75; 33 5.886,-3.75; 34 5.886,-3.25; 35 5.886,-2.75; 36 5.886,-2.25; 37 5.886,-1.75; 38 5.886,-1.25; 39 5.886,-0.75; 40 5.886,-0.25; 41 5.886,0.25; 42 5.886,0.75; 43 5.886,1.25; 44 5.886,1.75; 45 5.886,2.25; 46 5.886,2.75; 47 5.886,3.25; 48 5.886,3.75 | smd 0.3 x 1.2: 17 -3.75,-5.911; 18 -3.25,-5.911; 19 -2.75,-5.911; 20 -2.25,-5.911; 21 -1.75,-5.911; 22 -1.25,-5.911; 23 -0.75,-5.911; 24 -0.25,-5.911; 25 0.25,-5.911; 26 0.75,-5.911; 27 1.25,-5.911; 28 1.75,-5.911; 29 2.25,-5.911; 30 2.75,-5.911; 31 3.25,-5.911; 32 3.75,-5.911; 49 3.75,5.936; 50 3.25,5.936; 51 2.75,5.936; 52 2.25,5.936; 53 1.75,5.936; 54 1.25,5.936; 55 0.75,5.936; 56 0.25,5.936; 57 -0.25,5.936; 58 -0.75,5.936; 59 -1.25,5.936; 60 -1.75,5.936; 61 -2.25,5.936; 62 -2.75,5.936; 63 -3.25,5.936; 64 -3.75,5.936
DBZ_R-PDSO-G3 = smd 0.7 x 1: 1 -0.95,-1.1; 2 0.95,-1.1; 3 0,1.1
TSSOP16 = smd 0.35 x 1: 1 -1.95,-2.825; 2 -1.3,-2.825; 3 -0.65,-2.825; 4 0,-2.825; 5 0.65,-2.825; 6 1.3,-2.825; 7 1.95,-2.825; 8 2.6,-2.825; 9 2.6,2.825; 10 1.95,2.825; 11 1.3,2.825; 12 0.65,2.825; 13 0,2.825; 14 -0.65,2.825; 15 -1.3,2.825; 16 -1.95,2.825
SO08 = smd 0.6 x 2.2: 1 -1.905,-2.6; 2 -0.635,-2.6; 3 0.635,-2.6; 4 1.905,-2.6; 5 1.905,2.6; 6 0.635,2.6; 7 -0.635,2.6; 8 -1.905,2.6
SSOP28 = smd 0.381 x 1.905: 1 -4.55,-3.752; 2 -3.9,-3.752; 3 -3.25,-3.752; 4 -2.6,-3.752; 5 -1.95,-3.752; 6 -1.3,-3.752; 7 -0.65,-3.752; 8 0,-3.752; 9 0.65,-3.752; 10 1.3,-3.752; 11 1.95,-3.752; 12 2.6,-3.752; 13 3.25,-3.752; 14 3.9,-3.752; 15 3.9,3.752; 16 3.25,3.752; 17 2.6,3.752; 18 1.95,3.752; 19 1.3,3.752; 20 0.65,3.752; 21 0,3.752; 22 -0.65,3.752; 23 -1.3,3.752; 24 -1.95,3.752; 25 -2.6,3.752; 26 -3.25,3.752; 27 -3.9,3.752; 28 -4.55,3.752
SO14 = smd 0.66 x 2.032: 1 -3.81,-3.073; 2 -2.54,-3.073; 3 -1.27,-3.073; 4 0,-3.073; 5 1.27,-3.073; 6 2.54,-3.073; 7 3.81,-3.073; 8 3.81,3.073; 9 2.54,3.073; 10 1.27,3.073; 11 0,3.073; 12 -1.27,3.073; 13 -2.54,3.073; 14 -3.81,3.073
WQP_PJ_301M6 = drill 1.016 pad 1.778 octagon: P1 0,-5.715; P2 0,-3.175; P3 0,4.445 | hole 2.2: 0,0
2X5-1.27 = drill 0.61 pad 1.067 octagon: 1 -1.27,3.81; 2 0,3.81; 3 -1.27,2.54; 4 0,2.54; 5 -1.27,1.27; 6 0,1.27; 7 -1.27,0; 8 0,0; 9 -1.27,-1.27; 10 0,-1.27
1X06 = drill 1.016 pad 1.88 round: 1 0,0; 2 2.54,0; 3 5.08,0; 4 7.62,0; 5 10.16,0; 6 12.7,0
AVR_ICSP = drill 1.016 pad 1.88 octagon: 1 -1.27,5.08; 2 1.27,5.08; 3 -1.27,2.54; 4 1.27,2.54; 5 -1.27,0; 6 1.27,0; 7 -1.27,-2.54; 8 1.27,-2.54; 9 -1.27,-5.08; 10 1.27,-5.08
0603 = smd 0.85 x 0.7: 1 -0.9,0; 2 0.7,0
LED-BICOLOR-THROUGHHOLE = drill 0.7 round: 1 -2,0; 2 0,0; 3 2,0
HC49UP = smd 5.334 x 1.93: 1 -4.826,0; 2 4.826,0
SOT23-BEC = smd 1 x 1.4: B -0.95,-1.1; C 0,1.1; E 0.95,-1.1
R0603 = smd 1 x 1.1: 1 -0.85,0; 2 0.85,0
R1206 = smd 1.6 x 1.803: 1 -1.422,0; 2 1.422,0
ALPS_POT_VERTICAL_PS = drill 1 pad 1.88 square: P$1 -2.5,7; P$2 0,7; P$3 2.5,7 | drill 1.5 pad 2.54 octagon: P$4 -4.7,0; P$5 4.7,0
ALPS_POT_VERTICAL = drill 1 pad 1.88 square: P$1 -2.5,6.7; P$2 0,6.7; P$3 2.5,6.7 | drill 2.2 pad 3.175 octagon: P$4 -4.4,0; P$5 4.4,0
SJ_2S-NOTRACE = smd 0.635 x 1.27: 1 -0.45,0; 2 0.4,0
TACTILE-PTH = drill 1.016 pad 1.88 round: 1 -3.251,2.261; 2 3.251,2.261; 3 -3.251,-2.261; 4 3.251,-2.261
EVQ-Q2 = smd 3.2 x 1.2: A -3.4,-2; A' 3.4,-2; B -3.4,2; B' 3.4,2

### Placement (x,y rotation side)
C1  34.29,95.57 180 top
C2  17.46,94.3 90 top
C3  24.77,94.3 90 top
C4  30.16,92.71 270 top
C5  43.81,92.71 270 top
C6  10.79,87.31 0 top
C7  31.43,86.36 180 top
C8  5.71,84.77 0 top
C9  31.43,85.09 180 top
C10  41.91,82.55 0 top
C11  26.99,81.47 90 top
C12  60.96,78.42 270 top
C13  63.5,77.79 90 top
C14  4.76,76.52 90 top
C15  12.06,75.88 0 top
C16  26.99,74.61 90 top
C17  40.96,71.75 270 top
C18  42.23,71.75 270 top
C19  4.13,70.48 270 top
C20  28.89,71.44 270 top
C21  52.07,70.17 270 top
C22  38.73,69.22 0 top
C23  55.24,68.26 180 top
C24  64.45,68.26 0 top
C25  52.39,66.99 0 top
C26  6.35,64.77 270 top
C27  39.05,65.41 180 top
C28  18.73,62.23 180 top
C29  25.08,62.23 0 top
C30  40.01,60.01 270 top
C31  41.27,60.01 270 top
C32  41.59,53.34 90 top
C33  46.04,53.34 90 top
C34  50.48,53.34 90 top
C35  53.02,53.34 270 top
C36  18.73,51.44 180 top
C37  21.91,51.44 0 top
C38  25.08,51.44 0 top
C39  47.31,46.99 0 top
C40  53.66,46.99 90 top
C41  29.21,46.04 90 top
C42  36.83,46.04 90 top
C43  46.35,44.77 90 top
C44  61.59,43.5 0 top
C45  35.88,43.18 0 top
C46  15.24,29.53 270 top
C47  55.88,29.21 90 top
C48  12.7,27.3 270 top
C49  37.78,13.65 180 top
D1  19.05,101.28 90 top
D2  39.05,101.28 270 top
D3  27.94,53.02 180 top
F1  1.59,105.09 0 top
F2  67.63,105.09 0 top
F3  1.59,1.59 0 top
F4  67.63,1.59 0 top
IC1  7.94,93.03 90 top
IC2  34.92,77.47 270 top
IC3  12.06,73.34 180 top
IC4  61.59,73.34 270 top
IC5  7.3,70.48 0 top
IC6  46.99,60.96 270 top
IC7  21.91,56.83 0 top
IC8  41.59,45.09 270 top
J1  8.57,20.95 180 top
J2  21.59,20.95 180 top
J3  34.61,20.95 180 top
J4  47.62,20.95 180 top
J5  60.64,20.95 180 top
J6  8.57,6.35 180 top
J7  21.59,6.35 180 top
J8  34.61,6.35 180 top
J9  47.62,6.35 180 top
J10  60.64,6.35 180 top
JP1  47.31,69.22 0 bottom
JP2  65.72,94.3 270 bottom
JP3  28.57,101.92 270 bottom
L1  20.64,102.55 270 top
L2  37.47,102.55 270 top
L3  27.3,87.63 0 top
LED1  13.02,101.28 90 top
LED2  56.2,101.28 90 top
Q1  37.15,89.85 0 top
Q2  11.43,80.33 270 top
Q3  60.01,65.09 0 top
R1  10.79,102.87 270 top
R2  16.83,101.28 90 top
R3  10.79,99.69 90 top
R4  54.29,96.84 90 top
R5  55.88,96.84 90 top
R6  46.67,92.39 0 top
R7  51.12,92.39 0 top
R8  10.79,83.82 90 top
R9  18.1,84.01 180 top
R10  51.12,84.01 180 top
R11  7.62,80.64 0 top
R12  12.06,77.47 180 top
R13  6.35,76.52 270 top
R14  7.94,76.52 90 top
R15  9.53,76.52 90 top
R16  43.66,68.58 90 top
R17  45.09,68.58 90 top
R18  7.94,64.77 90 top
R19  9.53,64.77 270 top
R20  11.11,64.77 270 top
R21  18.73,65.41 180 top
R22  25.08,65.41 0 top
R23  20.95,64.77 270 top
R24  22.86,64.77 270 top
R25  18.73,63.82 0 top
R26  25.08,63.82 180 top
R27  52.7,60.01 270 top
R28  10.79,56.83 180 top
R29  34.61,56.83 180 top
R30  58.42,56.83 180 top
R31  18.73,49.85 0 top
R32  25.08,49.85 180 top
R33  42.23,48.9 180 top
R34  18.73,48.26 180 top
R35  25.08,48.26 0 top
R36  20.95,47.94 90 top
R37  22.86,47.94 90 top
R38  51.12,46.67 270 top
R39  32.07,46.04 90 top
R40  33.66,46.04 90 top
R41  35.24,46.04 270 top
R42  47.94,44.77 270 top
R43  49.53,44.77 90 top
R44  52.07,43.81 0 top
R45  8.57,36.83 180 top
R46  21.59,36.83 180 top
R47  34.61,36.83 180 top
R48  47.62,36.83 180 top
R49  60.64,36.83 180 top
R50  15.88,24.13 90 top
R51  37.78,12.06 0 top
R52  14.29,9.53 270 top
R53  28.89,9.53 270 top
R54  40.01,2.86 270 top
R55  42.23,2.86 90 top
R56  55.24,2.86 90 top
R57  16.19,8.26 270 top
SJ1  53.98,12.38 180 top
SW1  6.67,101.28 90 top
SW2  62.55,101.28 90 top
SW3  43.5,99.06 270 top
SW4  50.16,99.06 90 top
U$2  [ROHS_BIG]  32.07,58.1 0 bottom

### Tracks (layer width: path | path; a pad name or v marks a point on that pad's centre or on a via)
+3V3  (via drill 0.6)
  Top 0.254: SW4.B' SW4.B 48.16,93.57 47.62,93.03 47.62,92.5 | 47.62,92.5 R6.2 | C10.1 40.86,82.35 IC2.64 | C11.1 27.39,80.22 IC2.19 30.27,80.22 v30.48,80.01 | v39.69,83.82 39.69,84.45 40.64,85.41 42.86,85.41 43.5,86.04 47.94,86.04 v48.26,85.72 | v47.62,89.85 47.62,92.5 | v41.27,65.41 41.38,65.51 IC6.1 | 10.79,86.04 R8.2 | D3.2 26.99,53.34 27.3,53.02 29.84,53.02 32.07,55.24 32.07,63.18 30.16,65.09 30.16,67.94 29.84,68.26 29.84,72.39 | v42.23,68.58 43.08,69.43 R16.2 | IC2.48 38.82,71.44 39.37,71.44 40.11,72.17 40.11,72.61 | 29.84,72.39 29.84,72.71 30.48,73.34 v30.48,73.66 | 29.01,72.41 C20.1 | 29.01,72.41 IC2.32 | 29.01,72.41 29.03,72.39 29.84,72.39
  Top 0.305: 52.04,68.9 C21.+ 52.04,68.87 51.75,68.58 51.75,66.99 C25.1 50.48,66.99 49.21,65.72 49.21,65.09 49.44,64.86 IC6.27
  Top 0.406: 8.12,87.31 C8.+ | 8.12,87.31 C6.1 9.84,87.21 9.84,86.36 10.16,86.04 10.79,86.04 13.97,86.04 14.61,86.68 24.77,86.68 25.72,87.63 L3.1 26.41,86.41 v26.35,86.36 | v41.27,65.41 C27.1 | C10.1 | C10.1 39.37,82.55 37.15,80.33 37.15,77.15 37.78,76.52 37.78,74.93 40.11,72.61 C17.1 C18.1 42.33,72.71 42.55,72.71 43.66,71.6 R16.2 | C10.1 40.96,82.65 | v39.69,83.82 40.96,82.55 C10.1 | 8.12,87.31 8.12,87.77 5.44,90.45 IC1.3 | 49.53,68.9 52.04,68.9 | 49.53,68.9 49.53,72.39 48.9,73.03 JP1.1 | R16.2 43.55,69.53 | R16.2 R17.2 45.19,69.53 45.72,69.53 46.35,68.9 46.35,67.31 46.67,66.99 49.21,66.99 49.53,67.31 49.53,68.9
  Bottom 0.254: v48.26,85.72 47.62,86.36 v47.62,89.85
  Bottom 0.406: v42.23,68.58 41.27,67.63 v41.27,65.41 | v26.35,86.36 29.84,82.87 30.48,82.87 | 30.48,82.87 v30.48,80.01 v30.48,73.66 | v39.69,83.82 38.73,82.87 30.48,82.87
+3V3_A  (via drill 0.6)
  Top 0.254: 45.09,60.96 45.09,57.78 44.36,57.06 IC6.14 | L3.2 31.75,87.63 32.07,87.31 32.07,86.58 C7.1 C9.1 32.38,84.99 32.38,84.45 32.67,84.17 IC2.13 | 64.41,75.29 IC4.16 63.5,76.21 C13.1 62.13,76.94 61.91,77.15 60.99,77.15 C12.+ 59.66,77.12 v59.05,76.52 58.1,76.52 57.78,76.2 57.78,74.93 56.83,73.98 55.56,73.98 53.66,75.88 53.66,76.97 R10.P$1 | R50.2 15.88,26.35 15.24,26.99 C46.+
  Top 0.305: v47.31,60.96 45.09,60.96 IC6.8 41.38,60.96 C31.1 C30.1
  Top 0.406: R45.P$1 11.11,30.09 11.11,29.21 12.17,28.16 C48.1 15.17,28.16 C46.+ 15.85,28.23 15.88,28.26 24.13,28.26 | 24.13,28.26 37.15,28.26 | 37.15,28.26 50.16,28.26 | R46.P$1 24.13,30.09 24.13,28.26 | R47.P$1 37.15,30.09 37.15,28.26 | R48.P$1 50.16,30.09 50.16,28.26 | 59.69,60.96 v61.28,62.55 | 59.69,60.96 59.69,54.61 60.92,53.38 R30.P$1 | 59.69,60.96 v54.61,60.96 | IC7.4 21.91,52.7 21.06,51.85 C37.1 20.95,51.33 v20.95,50.16 | L3.2 27.94,87.56 27.94,86.36 26.99,85.41 25.08,85.41 24.77,85.72 21.91,85.72 20.6,84.42 R9.P$1 | v20.64,72.71 18.1,70.17 6.35,70.17 v6.03,70.48 5.18,71.33 C19.1 4.13,72.71 4.5,73.08 IC5.8 5.4,73.03 | v13.34,43.18 v20.95,43.18 24.13,43.18 28.29,47.34 C41.+ 29.21,49.85 31.11,51.75 36.2,51.75 | 36.2,51.75 36.2,58.74 38.31,60.86 C30.1 | R29.P$1 36.83,50.11 36.83,51.12 36.2,51.75 | v8.26,61.91 8.26,58.42 13.29,53.38 R28.P$1 | v59.05,37.62 59.21,37.47 60.64,37.47 61.28,36.83 61.28,34.45 63.18,32.54 63.18,30.17 R49.P$1 63.14,28.85 62.55,28.26 55.98,28.26 C47.1 55.78,28.26 50.16,28.26 | C44.1 60.64,43.6 60.64,44.13 60.96,44.45 v60.96,45.72
  Bottom 0.406: v59.05,37.62 59.05,42.55 60.96,44.45 v60.96,45.72 60.96,49.79 R30.P$1 60.96,49.87 | v59.05,76.52 59.05,70.48 61.28,68.26 v61.28,62.55 | v54.61,60.96 v47.31,60.96 | v20.64,72.71 20.6,72.75 R9.P$1 | R28.P$1 13.34,49.79 v13.34,43.18 | v20.95,43.18 v20.95,50.16 | v8.26,61.91 6.03,64.14 v6.03,70.48
AREF_-10  (via drill 0.6)
  Top 0.254: R23.2 R24.2 v22.86,62.55 | R36.2 R37.2 v22.86,50.16 | v22.86,67.63 22.54,67.31 16.51,67.31 13.34,64.14 v12.7,64.14 12.48,63.92 R20.2 | v10.79,73.03 11.12,73.34 IC3.2 11.21,74.54 C15.1 R12.2 9.63,77.47 R15.2
  Bottom 0.254: v22.86,50.16 v22.86,62.55 v22.86,67.63 | v12.7,64.14 12.7,71.12 v10.79,73.03
AUX_OUT
  Top 0.254: 43.16,57.78 IC6.13 42.15,57.71 41.91,57.47 41.91,56.52 42.23,56.2 42.86,56.2 44.42,54.64 C33.+
BOOT_FLASH  (via drill 0.6)
  Top 0.254: SW4.A' SW4.A 52.16,93.76 52.07,93.66 52.07,92.5 R7.2 51.97,89.95 v52.07,89.85 | v60.33,89.85 60.01,89.53 60.01,83.5 55.73,79.22 IC2.60
  Bottom 0.254: v60.33,89.85 v52.07,89.85
BRIGHTNESS_ATT  (via drill 0.6)
  Top 0.254: v58.42,33.97 57.94,33.5 10.32,33.5 8.57,31.75 R45.P$2 | v62.87,73.66 61.88,74.64 IC4.2
  Bottom 0.254: v58.42,33.97 58.74,34.29 60.96,34.29 61.59,34.92 61.59,38.42 65.09,41.91 65.09,71.44 v62.87,73.66
BRIGHTNESS_CV
  Top 0.254: IC2.14 32.17,82.02 31.75,81.6 30.16,81.6 28.26,83.5 26.04,83.5 25.72,83.19 25.72,80.33 23.18,77.79 23.18,73.66 19.05,69.53 5.71,69.53 5.4,69.22 IC5.1 5.4,64.14 5.71,63.82 6.25,63.82 C26.2 R18.1
BRIGHTNESS_POT  (via drill 0.6)
  Top 0.254: v10.79,34.92 11.59,34.13 57.31,34.13 58.1,34.92 60.01,34.92 v60.33,35.24 | v61.28,73.66 60.96,73.34 IC4.4
  Bottom 0.254: v10.79,34.92 10.79,37.78 11.75,38.73 11.75,40.96 10.79,41.91 R28.P$2 | v60.33,35.24 60.96,35.88 60.96,38.73 64.45,42.23 64.45,52.07 61.28,55.24 61.28,57.78 64.45,60.96 64.45,71.12 62.87,72.71 62.23,72.71 v61.28,73.66
CV_NORMALIZATION
  Top 0.254: R57.2 16.41,7.62 18.41,7.62 20.32,9.53 J7.P2
DAMP_ATT  (via drill 0.6)
  Top 0.254: R47.P$2 34.61,31.43 35.4,32.23 60.48,32.23 v60.96,32.7 | v66.04,73.34 IC4.13
  Bottom 0.254: v60.96,32.7 61.28,33.02 62.23,33.02 62.87,33.66 62.87,37.78 66.36,41.27 66.36,73.03 v66.04,73.34
DAMP_CV
  Top 0.254: R25.1 C28.2 17.88,61.49 18.1,61.28 IC7.14 18.1,58.42 18.41,58.1 25.72,58.1 26.35,58.74 26.35,60.96 27.62,62.23 27.62,66.36 24.45,69.53 24.45,77.15 26.52,79.22 IC2.21
DAMP_POT  (via drill 0.6)
  Top 0.254: v58.9,35.88 58.26,35.88 57.15,34.77 37.94,34.77 35.56,37.15 v35.56,38.1 | v60.96,72.07 60.34,72.69 IC4.5
  Bottom 0.254: v58.9,35.88 59.53,35.88 60.33,36.67 60.33,39.05 63.82,42.55 63.82,51.75 60.64,54.93 60.64,58.1 63.82,61.28 63.82,70.8 62.55,72.07 v60.96,72.07 | v35.56,38.1 35.56,44.45 34.61,45.4 R29.P$2
FM_CV
  Top 0.254: IC7.8 25.72,61.28 25.93,61.49 C29.2 R26.1 26.67,63.82 26.99,64.14 26.99,66.04 23.81,69.22 23.81,77.47 26.06,79.72 IC2.20
FREQUENCY_ATT  (via drill 0.6)
  Top 0.254: R46.P$2 21.59,31.43 23.02,32.86 59.21,32.86 v59.69,33.34 | v62.55,75.25 62.5,75.29 IC4.1
  Bottom 0.254: v59.69,33.34 60.01,33.66 61.28,33.66 62.23,34.61 62.23,38.1 65.72,41.59 65.72,72.07 v62.55,75.25
FREQUENCY_POT  (via drill 0.6)
  Top 0.254: 33.66,83.43 IC2.11 33.67,84.44 33.34,84.77 33.34,87 32.07,88.27 28.89,88.27 28.57,88.58 25.72,88.58 24.45,87.31 20.64,87.31 v20.32,87.63 | v20.32,85.72 20,85.41 20,79.06 19.37,78.42 18.41,78.42 18.1,78.11 R9.P$2
  Bottom 0.254: v20.32,85.72 v20.32,87.63
GEOMETRY_ATT  (via drill 0.6)
  Top 0.254: R48.P$2 47.62,31.43 47.78,31.59 61.75,31.59 v62.23,32.07 | v66.67,74.61 66.04,74.61 65.42,73.99 IC4.14
  Bottom 0.254: v62.23,32.07 63.18,32.07 66.99,35.88 66.99,74.3 v66.67,74.61
GEOMETRY_CV
  Top 0.254: R31.1 C36.2 17.88,52.17 18.1,52.39 IC7.1 18.1,54.93 20.64,57.47 26.04,57.47 26.99,58.42 26.99,60.64 28.26,61.91 28.26,66.67 25.08,69.85 25.08,76.83 26.97,78.72 IC2.22
GEOMETRY_POT  (via drill 0.6)
  Top 0.254: v34.29,80.96 34.29,82.23 34.17,82.35 IC2.10
  Bottom 0.254: v34.29,80.96 35.56,80.96 36.2,80.33 36.2,79.38 38.73,76.83 45.4,76.83 46.99,78.42 50.8,78.42 51.12,78.11 R10.P$2
GND  (via drill 0.6)
  Top 0.254: C31.2 41.38,59.05 42.23,59.05 42.27,59.01 IC6.11
  other vias: 36.51,65.41 41.27,69.53 57.15,72.07 58.42,78.42 37.78,58.74 21.27,61.91 27.62,77.15 26.99,71.75 28.26,82.23 24.13,56.2 10.48,67.94 44.13,81.6 29.21,86.04 53.34,50.16 48.26,48.58 32.38,43.18 3.81,86.36 13.34,93.03 13.34,72.71 43.81,95.57 32.38,93.34 50.16,93.98 43.5,101.6 22.86,92.08 19.37,92.08 33.81,73.82 34.29,61.28 31.75,78.11 45.09,64.14 57.15,43.81 38.73,41.91 21.59,56.2 15.56,92.08 26.67,92.08 18.73,57.15 12.06,52.7 13.97,61.59 10.48,88.9 58.42,62.23 27.62,44.13 1.27,45.72 1.27,55.88 1.27,60.96 1.27,73.98 1.27,101.6 6.35,105.41 62.23,105.41 67.94,101.6 1.27,15.24 1.27,5.08 5.08,1.27 25.4,1.27 50.8,1.27 67.94,5.08 63.5,21.59 62.23,46.67 61.28,60.64 57.15,87.63 22.86,81.28 40.01,92.71 21.59,70.17 34.29,54.61 56.2,47.62 57.15,54.61 27.94,30.48 41.27,30.48 53.98,30.48 27.94,26.35 12.7,20.32 27.94,21.59 41.27,21.59 53.98,21.59 15.24,21.59 27.94,5.71 53.34,5.71 37.15,81.92 45.4,78.11 59.69,46.67 48.26,60.01 5.08,50.8 6.03,96.84 1.27,95.89 1.27,93.98 1.27,92.08 1.27,90.17 1.27,88.27 3.81,88.27 5.4,88.27 1.27,86.36 5.4,86.36 6.99,86.36 57.15,66.99 62.55,66.99 53.98,69.85 5.08,60.96 41.27,26.67 53.98,26.67 15.24,5.71 16.51,32.38 10.48,71.75 27.62,56.83 13.34,87.31
  pour Bottom: 0,106.68 0,0 69.22,0 69.22,106.68
  pour Top: 0,106.68 69.22,106.68 69.22,0 0,0
I2C_SCL  (via drill 0.6)
  Top 0.254: IC6.24 50.7,62.87 48.58,62.87 44.77,66.67 44.13,66.67 43.66,67.15 R16.1 43.55,67.63 36.2,67.63 35.56,68.26 v35.56,68.9 | v33.02,76.52 32.38,75.88 31.43,75.88 30.77,75.22 IC2.29
  Bottom 0.254: v33.02,76.52 33.02,74.3 32.7,73.98 32.7,70.8 33.97,69.53 34.92,69.53 v35.56,68.9
I2C_SDA  (via drill 0.6)
  Top 0.254: IC6.23 50.71,62.23 48.26,62.23 47.47,63.02 | v32.07,74.93 31.86,74.72 IC2.30 | v34.29,68.58 34.29,67.94 34.92,67.94 35.88,66.99 42.86,66.99 43.81,66.04 44.45,66.04 47.47,63.02 | R17.1 45.09,67.31 48.26,64.14 v48.58,64.14 | v46.67,62.55 46.99,62.55 47.47,63.02 | 47.47,63.02
  Bottom 0.254: v34.29,68.58 33.97,68.58 32.07,70.48 v32.07,74.93 | v48.58,64.14 46.99,62.55 v46.67,62.55
I2S_LRCK
  Top 0.254: IC6.5 44.41,62.91 44.77,62.55 44.77,61.91 44.45,61.59 43.25,61.59 IC6.7 43.22,61.59 42.23,61.59 41.59,62.23 35.24,62.23 32.38,65.09 32.07,65.09 31.43,65.72 31.43,68.58 31.18,68.84 IC2.33
I2S_SCK  (via drill 0.6)
  Top 0.254: IC6.3 43.16,64.14 36.2,64.14 34.92,65.41 v34.92,66.04 | v32.38,66.04 32.07,66.36 32.07,68.9 31.68,69.29 IC2.34
  Bottom 0.254: v32.38,66.04 v34.92,66.04
I2S_SIN
  Top 0.254: IC6.6 43.21,62.23 42.23,62.23 41.59,62.87 35.56,62.87 33.34,65.09 33.34,66.67 32.7,67.31 32.7,69.22 32.17,69.74 IC2.35
I2S_SOUT
  Top 0.254: 43.18,63.5 IC6.4 35.82,63.56 33.97,65.41 33.97,66.99 33.34,67.63 33.34,69.53 32.67,70.19 IC2.36
IN_1
  Top 0.254: R27.1 52.16,60.31 IC6.20
IN_2
  Top 0.254: IC6.19 50.71,59.69 49.53,59.69 48.58,58.74 48.58,54.61 49.21,53.98 49.21,50.16 50.48,48.9 52.07,48.9 52.67,48.29 C40.+
JTCK  (via drill 0.6)
  Top 0.254: v44.13,72.71 43.12,73.72 IC2.49
  Bottom 0.254: v44.13,72.71 44.45,72.39 46.04,72.39 46.67,71.75 JP1.4
JTDI
  Top 0.254: JP1.8 46.99,69.22 45.72,70.48 45.72,72.71 44.21,74.22 IC2.50
JTDO
  Top 0.254: JP1.6 46.35,71.44 46.35,73.03 42.66,76.72 IC2.55
JTMS  (via drill 0.6)
  Top 0.254: v37.78,73.34 37.67,73.23 IC2.46
  Bottom 0.254: JP1.2 45.4,73.03 44.77,73.66 43.5,73.66 43.18,73.34 v37.78,73.34
MAIN_OUT
  Top 0.254: IC6.12 42.17,58.36 41.27,57.47 41.27,56.2 41.59,55.88 C32.+
MUX_ADDR_0
  Top 0.254: IC4.11 64.39,72.07 63.18,72.07 61.28,70.17 57.63,70.17 52.86,74.93 46.99,74.93 43.2,78.72 IC2.59
MUX_ADDR_1
  Top 0.254: IC4.10 63.45,71.39 61.59,69.53 57.47,69.53 52.55,74.45 46.67,74.45 42.91,78.22 IC2.58
MUX_ADDR_2
  Top 0.254: IC4.9 63.76,70.74 61.91,68.9 57.31,68.9 52.23,73.98 46.35,73.98 42.61,77.72 IC2.57
MUXED_POTS  (via drill 0.6)
  Top 0.254: 58.76,73.98 IC4.3 57.8,73.99 57.15,73.34 55.24,73.34 53.02,75.56 47.31,75.56 46.67,76.2 v46.67,76.52 | IC2.9 34.67,82.48 34.92,82.23 34.92,81.6 35.24,81.28 v35.24,79.69
  Bottom 0.254: v35.24,79.69 35.24,79.38 38.42,76.2 46.35,76.2 v46.67,76.52
N$1
  Top 0.254: J1.P3 6.03,16.51 2.22,20.32 2.22,39.37 10.48,47.62 13.97,47.62 14.92,48.58 14.92,53.02 9.53,58.42 R19.2
N$2
  Top 0.254: R20.1 R19.1 R18.2 C26.1 6.35,66.36 6.67,66.67 IC5.2
N$3
  Top 0.254: J7.P3 11.43,1.91 9.84,3.49 5.71,3.49 5.08,4.13 5.08,16.51 1.59,20 1.59,39.69 6.67,44.77 6.67,52.39 3.17,55.88 3.17,74.3 2.54,74.93 2.54,77.47 3.49,78.42 7.62,78.42 7.94,78.11 R14.2
N$4
  Top 0.254: R22.2 25.93,66.14 25.4,66.67 17.46,66.67 16.19,65.41 16.19,60.96 13.65,58.42 13.65,55.56 15.56,53.66 15.56,48.26 14.29,46.99 10.79,46.99 6.35,42.55 6.35,36.2 2.86,32.7 2.86,20.64 5.71,17.78 9.21,17.78 9.84,17.14 19.68,17.14 20.32,16.51 J2.P3
N$5
  Top 0.254: IC7.9 24.45,61.28 24.23,61.49 C29.1 R26.2 R22.1 24.02,65.62 R24.1
N$6
  Top 0.254: R34.2 17.88,47.41 16.19,45.72 11.43,45.72 7.62,41.91 7.62,35.56 4.13,32.07 4.13,21.27 6.35,19.05 9.84,19.05 10.48,18.41 22.54,18.41 23.18,17.78 35.24,17.78 35.88,17.14 45.72,17.14 46.35,16.51 J4.P3
N$7
  Top 0.254: IC2.5 36.67,87.47 37.78,88.58 41.27,88.58 41.97,89.28 Q1.2 43.81,89.85 C5.2
N$8
  Top 0.254: IC2.6 36.17,87.33 34.92,88.58 33.02,88.58 32.32,89.28 Q1.1 30.16,89.85 C4.2
N$9
  Top 0.254: J6.P3 6.35,1.91 4.45,3.81 4.45,16.19 0.95,19.68 0.95,40.01 6.03,45.09 6.03,52.07 2.54,55.56 2.54,73.98 1.91,74.61 1.91,78.11 4.45,80.64 R11.1
N$10
  Top 0.254: R21.2 17.14,65.41 16.83,65.09 16.83,61.59 17.46,60.96 17.46,55.56 16.19,54.29 16.19,47.94 14.61,46.35 11.11,46.35 6.99,42.23 6.99,35.88 3.49,32.38 3.49,20.95 6.03,18.41 9.53,18.41 10.16,17.78 22.23,17.78 22.86,17.14 32.7,17.14 33.34,16.51 J3.P3
N$11
  Top 0.254: IC7.13 19.37,61.28 19.58,61.49 C28.1 R25.2 R21.1 19.8,65.62 R23.1
N$12
  Top 0.254: R1.2 11.01,102.23 12.38,102.23 13.02,102.87 LED1.3
N$13
  Top 0.254: C22.1 37.78,70.17 38.17,70.56 IC2.47
N$14
  Top 0.254: C14.1 R13.2 R14.1 | R14.1 R15.1 | R14.1 IC5.6
N$15
  Top 0.254: IC7.2 19.37,52.39 19.58,52.17 C36.1 R31.2 R34.1 19.58,47.41 20,46.99 20.85,46.99 R36.1
N$16
  Top 0.406: IC1.2 12.79,95.25 14.92,95.25 16.37,96.7 C2.+ 17.46,98.11 16.83,98.74 R2.1
N$17
  Top 0.254: IC6.16 50.67,57.78 49.53,57.78 49.21,57.47 49.21,55.24 49.82,54.64 C34.+ 50.51,54.61 51.75,54.61 52.17,54.19 C35.1
N$18  (via drill 0.6)
  Top 0.254: R54.1 40.01,7.62 38.63,8.99 R51.2 C49.1 41.91,13.65 42.86,14.61 63.18,14.61 v64.14,15.56 | v64.14,12.38 64.45,12.7 66.04,12.7 68.26,14.92 68.26,38.42 64.45,42.23 54.93,42.23 53.98,43.18 53.98,44.45 53.66,44.77 C40.-
  Bottom 0.254: v64.14,15.56 63.82,15.24 63.82,14.92 63.82,13.02 63.82,12.7 v64.14,12.38
N$19
  Top 0.254: C16.1 27.55,74.22 IC2.31
N$20
  Top 0.254: R52.2 14.19,8.57 13.02,8.57 12.06,9.53 J6.P2
N$21
  Top 0.254: J8.P3 34.71,2.01 R54.2
N$22
  Top 0.254: R3.2 11.01,100.33 12.38,100.33 13.02,99.69 LED1.1
N$23
  Top 0.254: C33.- 46.04,49.85 46.35,49.53 48.58,49.53 49.53,48.58 R43.2 49.73,45.82 R38.2
N$24
  Top 0.406: D1.A 19.32,103.45 L1.1
N$25
  Top 0.254: IC8.6 45.4,44.45 45.94,43.92 C43.1 R42.2 R43.1 49.63,43.81 R44.1
N$26
  Top 0.254: J5.P3 49.53,16.51 48.26,17.78 36.2,17.78 35.56,18.41 23.5,18.41 22.86,19.05 15.88,19.05 9.53,25.4 6.67,25.4 4.76,27.3 4.76,31.75 8.26,35.24 8.26,41.59 11.75,45.09 23.81,45.09 25.93,47.2 R35.2
N$27
  Top 0.254: LED2.3 54.29,101.38 R4.2
N$28
  Top 0.254: R42.1 C43.2 45.51,45.62 45.4,45.72 IC8.7 42.86,45.72 42.55,45.4 42.55,42.23 43.18,41.59 64.14,41.59 67.63,38.1 67.63,15.24 65.72,13.34 63.82,13.34 61.28,10.79 57.15,10.79 55.24,8.89 R56.2
N$29
  Top 0.254: J10.P3 60.54,2.01 R56.1
N$30
  Top 0.254: R37.1 22.96,46.99 23.81,46.99 24.23,47.41 R35.1 R32.2 C38.1 24.23,52.17 24.45,52.39 IC7.6
N$31
  Top 0.254: R40.2 33.66,47.62 34.29,48.26 39.37,48.26 40.01,48.9 R33.2 41.59,49.11 C32.-
N$32
  Top 0.254: IC8.2 37.78,45.72 37.25,45.19 C42.1 R41.2 R40.1 R39.1
N$33
  Top 0.254: R55.2 42.23,10.48 45.72,13.97 63.82,13.97 66.36,16.51 66.36,32.38 62.87,35.88 62.87,38.1 60.64,40.32 42.55,40.32 41.27,41.59 41.27,46.04 40.32,46.99 IC8.1 36.93,46.99 C42.2 R41.1
N$34
  Top 0.254: J9.P3 47.52,2.01 R55.1
N$35
  Top 0.254: LED2.1 55.88,98.97 R5.2
N$36
  Top 0.406: D2.C 38.78,103.45 L2.1
N$37  (via drill 0.6)
  Top 0.254: v38.73,79.38 38.42,79.06 38.42,77.79 39.05,77.15 39.05,75.88 39.72,75.22 IC2.52 | v49.53,81.92 49.53,83.19 56.52,90.17 56.52,94.93 57.15,95.57 57.15,103.82 56.52,104.46 14.61,104.46 13.97,103.82 13.97,98.74 13.34,98.11 12.38,98.11 11.75,98.74 10.9,98.74 R3.1
  Bottom 0.254: v38.73,79.38 39.05,79.38 39.69,80.01 48.26,80.01 49.53,81.28 v49.53,81.92
N$38
  Top 0.254: R50.1 15.98,23.18 17.78,23.18 18.73,24.13 J2.P2
N$39
  Top 0.254: J8.P2 31.75,9.53 30.9,8.68 R53.2
N$40  (via drill 0.6)
  Top 0.254: R4.1 54.29,90.17 52.39,88.27 41.91,88.27 41.59,87.95 38.42,87.95 v37.78,87.31 | v34.61,85.09 35.17,84.52 IC2.8
  Bottom 0.254: v37.78,87.31 35.56,85.09 v34.61,85.09
N$41
  Top 0.254: IC6.25 52.33,63.56 52.39,63.5 59.37,63.5 60.96,65.09 Q3.2 64.77,65.15 64.77,66.36 65.3,66.89 C24.2
N$42
  Top 0.254: IC6.26 52.15,64.21 52.39,64.45 55.24,64.45 55.24,65.02 Q3.1 55.18,66.74 54.29,67.63 54.29,68.16 C23.2
N$43  (via drill 0.6)
  Top 0.254: v39.37,78.11 39.37,77.79 39.69,77.47 39.69,76.2 40.17,75.72 IC2.53 | v50.8,81.6 50.8,83.5 57.15,89.85 57.15,94.61 57.78,95.25 57.78,104.14 56.83,105.09 11.43,105.09 10.79,104.46 R1.1
  Bottom 0.254: v39.37,78.11 39.37,78.74 40.01,79.38 48.58,79.38 v50.8,81.6
N$44  (via drill 0.6)
  Top 0.254: R5.1 55.88,90.49 48.26,82.87 v48.26,82.23 | v39.05,80.64 38.73,80.64 37.78,79.69 37.78,77.47 38.42,76.83 38.42,75.56 39.26,74.72 IC2.51
  Bottom 0.254: v39.05,80.64 47.94,80.64 48.26,80.96 v48.26,82.23
N$45  (via drill 0.6)
  Top 0.254: v31.75,39.37 32.07,39.69 60.33,39.69 62.39,37.62 62.39,35.4 65.72,32.07 65.72,19.68 v64.14,18.1 | R39.2 31.96,46.99 31.43,46.99 30.8,46.35 v30.8,43.18
  Bottom 0.254: v30.8,43.18 31.75,42.23 v31.75,39.37 | v64.14,18.1 63.18,17.14 63.18,10.79 61.91,9.53 J10.P2
N$46  (via drill 0.6)
  Top 0.254: R44.2 53.02,43.71 v53.02,42.47 | v62.23,17.78 65.09,20.64 65.09,31.75 61.91,34.92 61.91,37.15 60.01,39.05 50.48,39.05 v50.16,38.73 | SJ1.1 57.15,12.38 58.1,13.34 61.91,13.34 v62.23,13.02
  Bottom 0.254: v62.23,13.02 62.55,13.34 62.55,17.46 v62.23,17.78 | 50.32,38.89 v50.16,38.73 50.16,39.61 v53.02,42.47
N$47
  Top 0.254: J9.P2 49.53,9.53 52.39,12.38 SJ1.2
N$56
  Top 0.406: 23.5,101.92 JP3.2 | 23.5,101.92 JP3.1 | L1.2 20.7,101.92 23.5,101.92
N$64
  Top 0.406: JP3.10 33.66,101.92 | 33.66,101.92 JP3.9 | L2.2 37.4,101.92 33.66,101.92
N$66
  Top 0.254: R11.2 9.21,80.64 9.84,81.28 Q2.B
NORMALIZATION_PROBE  (via drill 0.6)
  Top 0.254: v6.99,32.38 6.99,33.02 8.89,34.92 8.89,41.27 12.06,44.45 24.13,44.45 26.99,47.31 26.99,49.85 27.94,50.8 D3.3 28.09,52.07 29.84,52.07 32.7,54.93 32.7,63.5 30.8,65.41 30.8,68.26 30.48,68.58 30.48,72.39 30.8,72.71 33.97,72.71 34.17,72.5 IC2.39 | v7.3,14.61 9.21,14.61 13.44,10.38 R52.1 14.5,10.16 16.19,10.16 | 16.19,10.16 20.32,10.16 20.95,10.79 22.23,10.79 22.64,10.38 R53.1 | 16.19,10.16 R57.1
  Bottom 0.254: v6.99,32.38 4.76,32.38 3.49,31.11 3.49,18.41 v7.3,14.61
POSITION_ATT  (via drill 0.6)
  Top 0.254: v67.63,76.2 66.67,76.2 65.12,74.64 IC4.15
  Bottom 0.254: R49.P$2 60.64,29.21 61.59,28.26 64.14,28.26 66.36,30.48 66.36,34.29 67.63,35.56 v67.63,76.2
POSITION_CV
  Top 0.254: R32.1 C38.2 25.93,52.17 25.72,52.39 IC7.7 | IC7.7 25.93,53.98 | IC2.23 27.42,78.22 25.72,76.52 25.72,70.17 28.89,66.99 28.89,61.59 27.62,60.33 27.62,58.1 25.72,56.2 IC7.7
POSITION_POT
  Top 0.254: IC4.12 65.1,72.69 67.94,69.85 67.94,61.91 65.09,59.05 65.09,51.44 61.91,48.26 58.74,48.26 58.42,48.58 R30.P$2
RESET  (via drill 0.6)
  Top 0.254: 45.5,99.06 SW3.B' 45.5,93.25 45.72,93.03 45.72,92.5 R6.1 | 45.5,99.06 SW3.B | v36.51,88.9 36.51,91.44 40.01,94.93 40.01,97.47 41.59,99.06 45.5,99.06 | v34.92,87.31 35.67,86.56 IC2.7 35.67,81.8 36.2,81.28 36.2,79.38 34.61,77.79 v34.61,74.93
  Bottom 0.254: v34.92,87.31 v36.51,88.9 | v34.61,74.93 34.61,74.3 37.15,71.75 42.55,71.75 46.35,67.94 JP1.10
RX  (via drill 0.6)
  Top 0.254: v36.83,75.56 36.83,73.66 36.17,73 IC2.43 | JP2.4 66.67,86.68 66.99,86.36 66.99,83.5 66.36,82.87 61.28,82.87 56.83,78.42 56.83,75.25 v56.52,74.93
  Bottom 0.254: v36.83,75.56 37.47,74.93 44.77,74.93 45.09,74.61 56.2,74.61 v56.52,74.93
STRUM
  Top 0.254: R8.1 10.79,82.55 11.43,81.92 11.75,81.92 12.53,81.13 Q2.C 13.65,80.33 13.97,80.01 13.97,75.25 14.61,74.61 21.59,74.61 21.91,74.93 21.91,78.42 24.45,80.96 24.45,83.82 25.4,84.77 28.89,84.77 30.16,83.5 31.08,83.5 IC2.16
SW_MODE
  Top 0.254: SW2.4 SW2.3 59.37,92.6 59.37,83.82 55.27,79.72 IC2.61
SW_POLYPHONY
  Top 0.254: SW1.4 10.12,105.73 57.15,105.73 58.74,104.14 58.74,84.14 54.82,80.22 IC2.62
  Bottom 0.254: SW1.3 SW1.4
TX  (via drill 0.6)
  Top 0.254: v36.2,77.15 35.88,76.83 35.88,73.66 35.67,73.46 IC2.42 | v55.88,76.2 55.88,78.42 61.59,84.14 JP2.5
  Bottom 0.254: v36.2,77.15 36.51,77.15 38.1,75.56 45.09,75.56 45.4,75.25 54.93,75.25 v55.88,76.2
V_OCT_CV
  Top 0.254: IC2.15 31.68,82.47 31.43,82.23 30.48,82.23 28.57,84.14 25.72,84.14 25.08,83.5 25.08,80.64 22.54,78.11 22.54,74.61 21.91,73.98 20.64,73.98 17.46,70.8 7.62,70.8 6.67,71.75 IC5.7 6.67,74.3 6.35,74.61 4.13,74.61 3.81,74.93 3.81,77.15 4.03,77.37 C14.2 R13.1
VCC  (via drill 0.6)
  Top 0.406: IC8.8 C39.1 46.35,47.09 v46.35,48.26 | v40.01,40.96 39.37,40.32 12.06,40.32 10.79,39.05 v10.16,39.05 | v2.54,99.69 6.35,99.69 6.99,99.06 6.99,97.47 7.94,96.52 13.34,96.52 14.92,98.11 14.92,102.23 15.39,102.7 R2.2 16.83,101.6 17.14,101.28 18.41,101.28 19.05,100.65 20,100.65 23.18,97.47 24.77,97.47 C3.+ 22.68,96.7 20,99.38 D1.C
  Bottom 0.406: v46.35,48.26 46.35,44.77 42.55,40.96 v40.01,40.96 | v10.16,39.05 9.84,39.05 2.54,46.35 v2.54,99.69
VEE  (via drill 0.6)
  Top 0.254: R12.1 13.02,77.57 v13.02,79.06
  Top 0.406: IC8.4 C45.2 36.73,42.44 35.88,41.59 11.11,41.59 v10.16,40.64 | v13.97,88.58 14.92,89.53 26.67,89.53 28.57,91.44 28.57,94.93 30.8,97.16 33.97,97.16 35.56,95.57 C1.- 37.78,95.57 39.05,96.84 D2.A
  Bottom 0.254: 3.81,79.06 v13.02,79.06
  Bottom 0.406: v13.97,88.58 11.75,88.58 3.81,80.64 3.81,79.06 3.81,46.99 v10.16,40.64

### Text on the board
tNames: RESET | SYSBOOT | Rings | cc-by-sa | Olivier Gillet | 2015. v3
bNames: stripe | Red | +12V | GND | -12V | GND | <TX | JTAG | Rings | cc-by-sa Olivier Gillet, 2015. v3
